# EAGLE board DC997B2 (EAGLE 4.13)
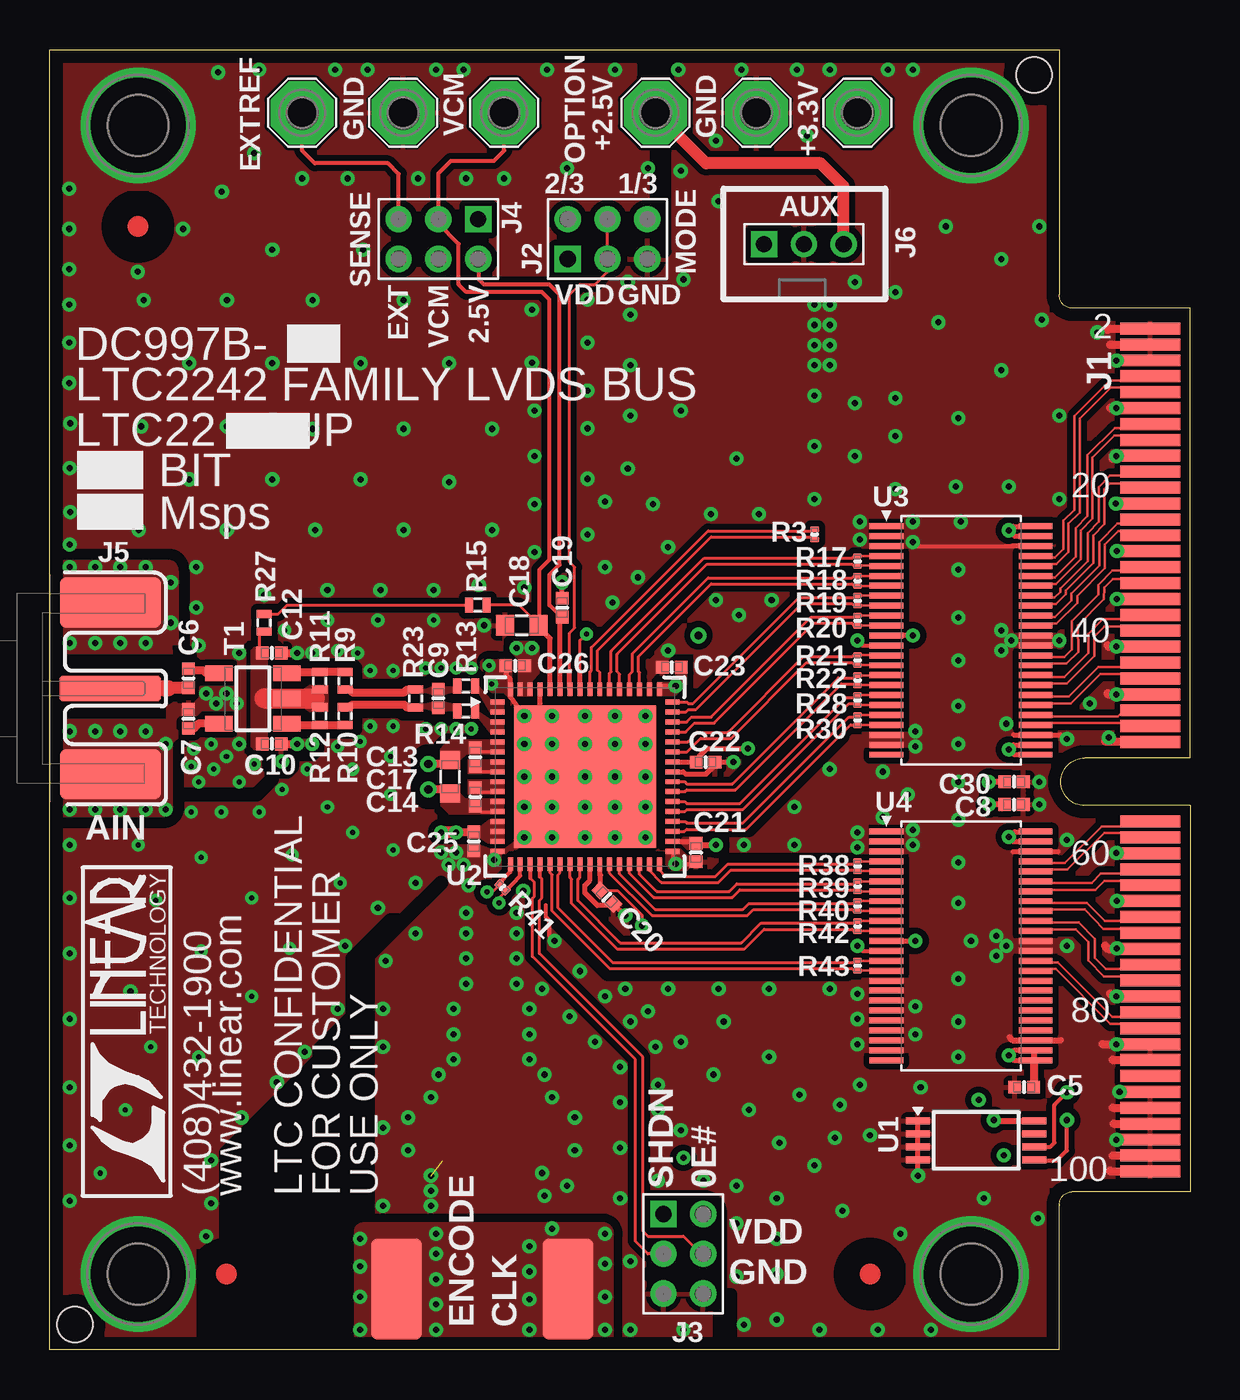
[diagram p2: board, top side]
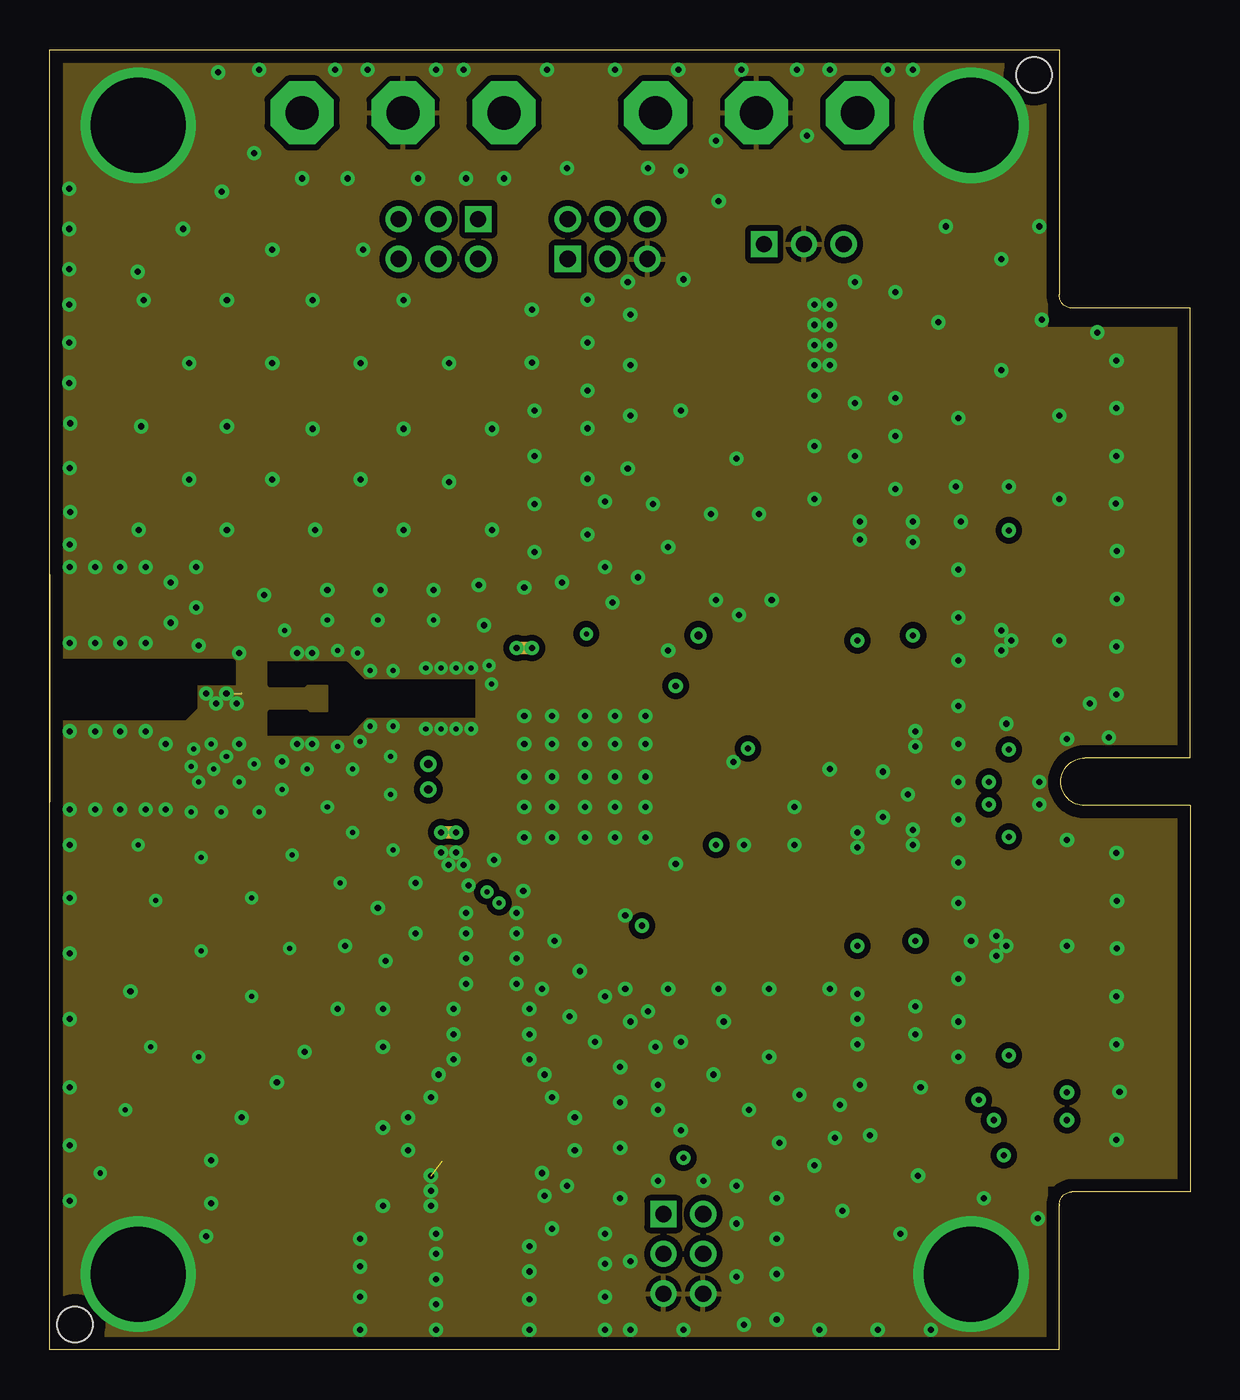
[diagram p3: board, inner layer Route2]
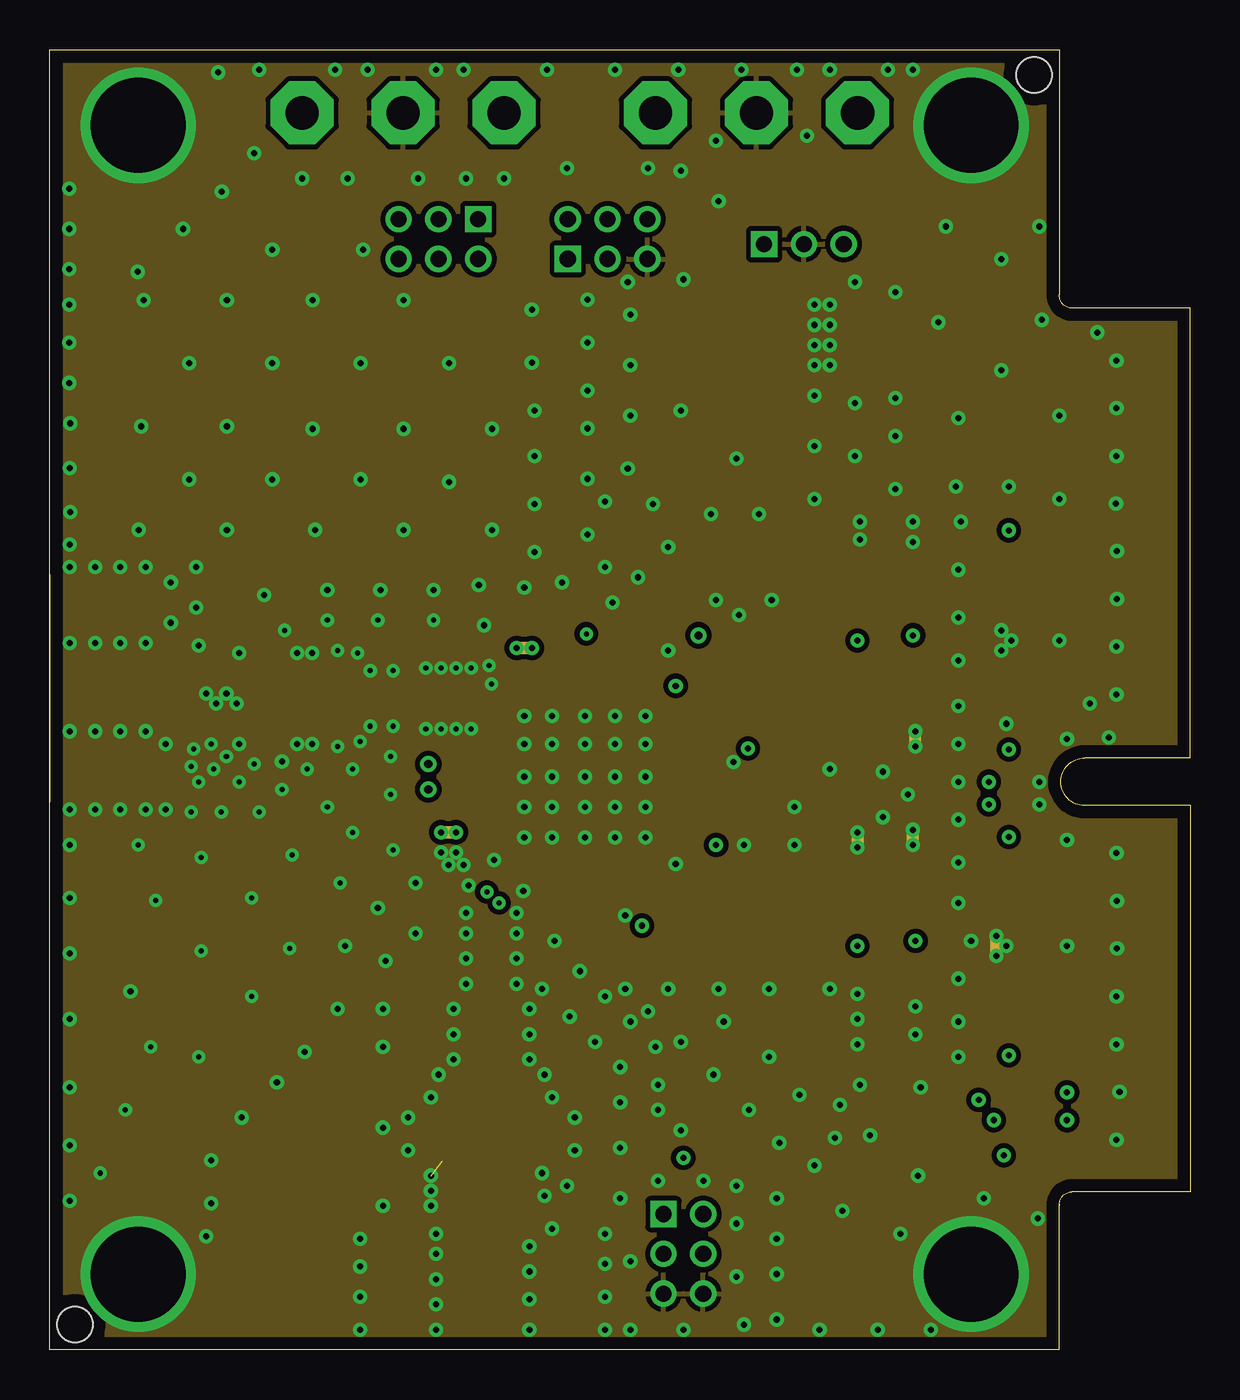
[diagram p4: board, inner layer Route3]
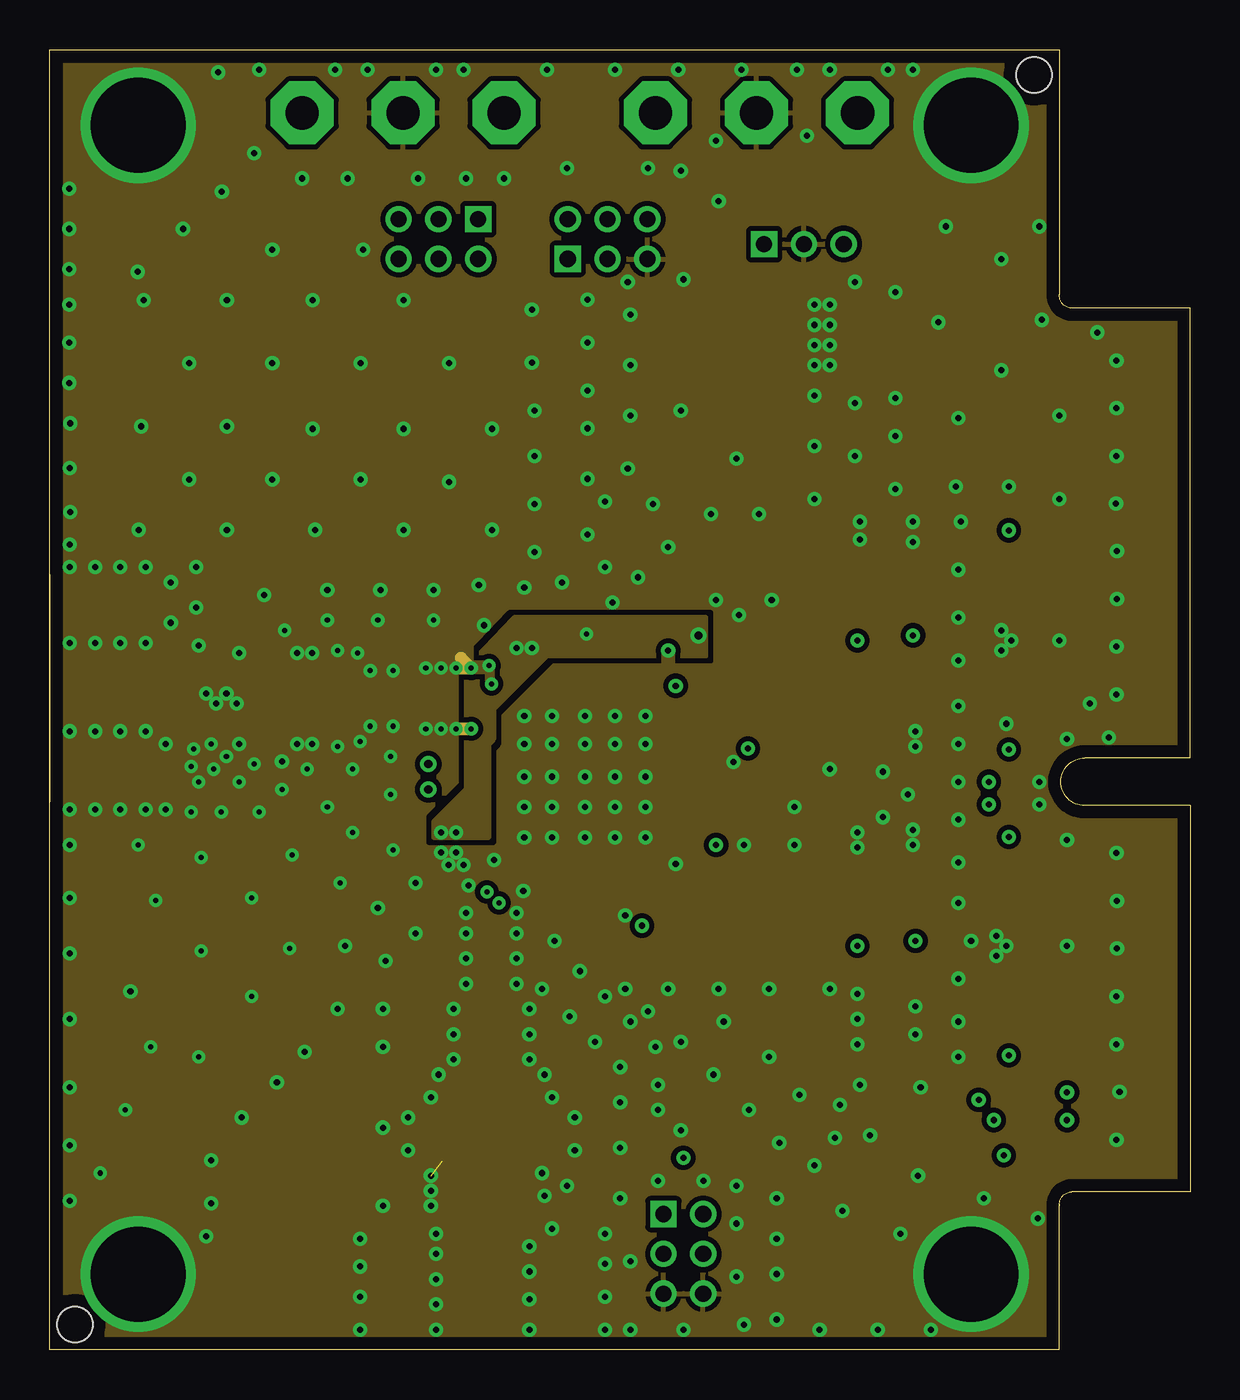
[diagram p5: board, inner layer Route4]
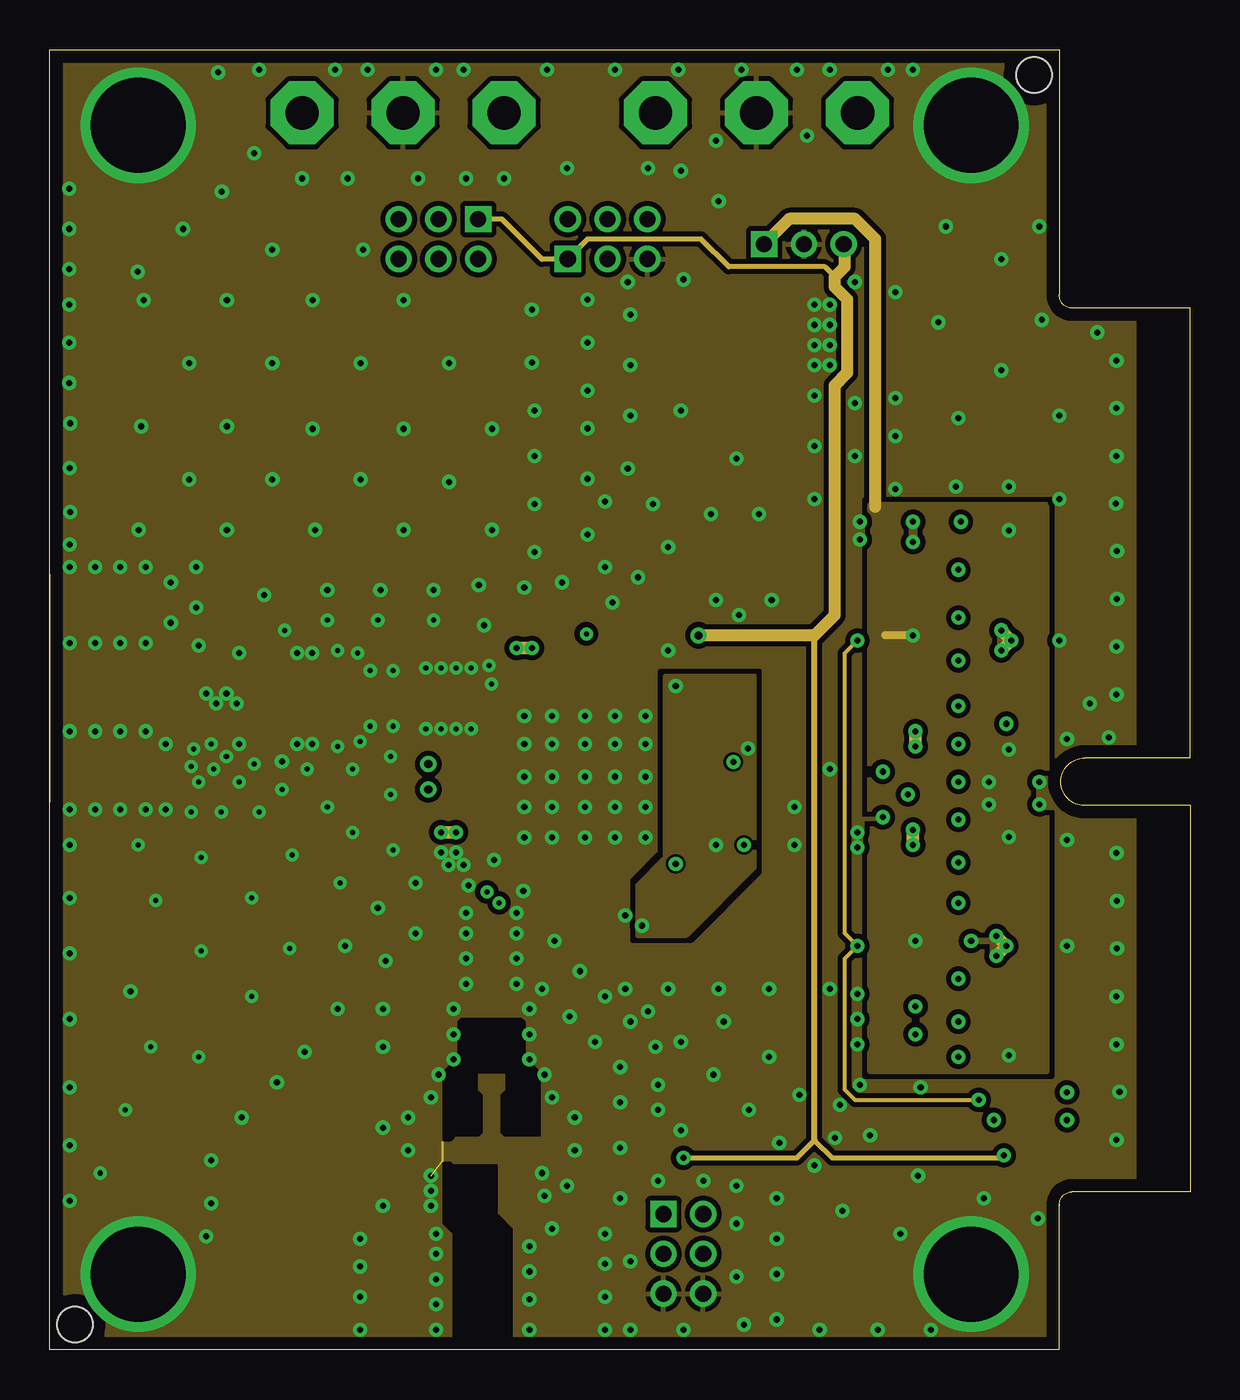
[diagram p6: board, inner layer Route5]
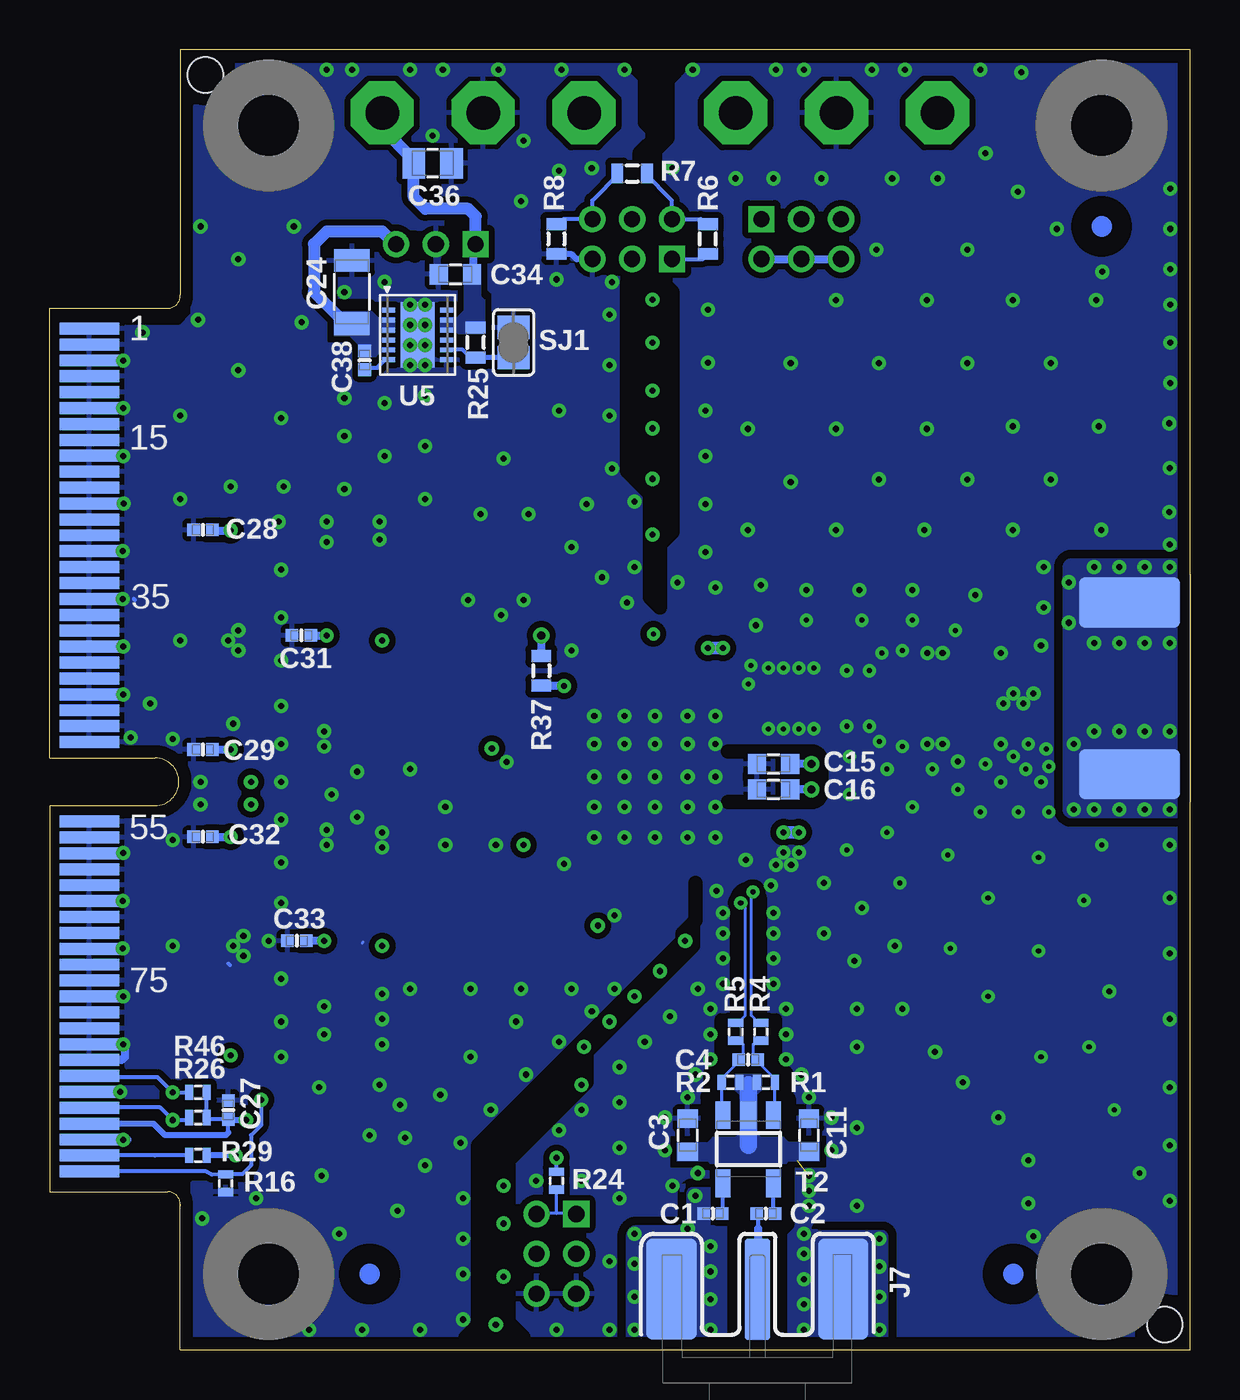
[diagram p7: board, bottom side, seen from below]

Size 57.37 x 65.41 mm. Coordinates in mm from the lower left corner, seen from the top.
Outline: 50.8,53.09 50.8,65.41 0,65.41 0,0 50.8,0 50.8,7.31
Copper layers (1+2*3+4*5+16): Top 0.035mm / dielectric 0.1524mm / Route2 0.035mm / dielectric 0.3556mm / Route3 0.035mm / dielectric 0.254mm / Route4 0.035mm / dielectric 0.3556mm / Route5 0.035mm / dielectric 0.1524mm / Bottom 0.035mm
Design rules "default": minimum track width 5mil, minimum drill 10mil, track to track 5mil, track to pad 5mil, pad to pad 5mil, via to via 5mil, smd to smd 5mil, copper to edge 25mil, drill to drill 15mil, minimum pad ring 10mil, minimum via ring 8mil, stop-mask expansion 3mil, vias tented up to drill 13mil, thermal gap 10mil
tRestrict: area 26.9,24.9 to 27.5,25.2; area 23.1,28.2 to 23.3,29.3; area 29.8,32.4 to 30.6,32.9; area 38.6,55 to 39.1,56.3; area 36.7,55 to 37.2,56.3; area 41.2,18.2 to 43,18.4; area 41.2,17.7 to 43,17.9; area 41.2,17.2 to 43,17.4; area 41.2,16.7 to 43,16.9; area 41.2,16.2 to 43,16.4; area 41.2,15.7 to 43,15.9; area 41.2,15.2 to 43,15.4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; 74 lines
bRestrict: area 20.8,14 to 23.6,16.6; area 25,0.6 to 36.4,21.5; area 25.4,37.3 to 28.3,64.8; area 43.2,53 to 43.3,54.1; area 41.3,52.3 to 42.7,52.6; 47 lines
vRestrict: area 6.7,31.5 to 25.5,37.8

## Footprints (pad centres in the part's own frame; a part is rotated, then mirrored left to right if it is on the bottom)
TOOLING_HOLE_0R067 = hole 1.778: 0,0
KEYSTONE_8831_GND = drill 4.775 pad 5.588 round: 1 0,0
C0402 = smd 0.635 x 0.635: 1 -0.472,0; 2 0.472,0
C0603 = smd 0.914 x 1.016: 1 -0.837,0; 2 0.837,0
C1206 = smd 1.143 x 1.778: 1 -1.591,0; 2 1.591,0
C0805 = smd 1.143 x 1.524: 1 -0.952,0; 2 0.952,0
MEC8-150-02-L-D-EDGE_CONN-NEW-ORIGIN = smd 3 x 0.6 bottom: 1 3.3,22.8; 3 3.3,22; 5 3.3,21.2; 7 3.3,20.4; 9 3.3,19.6; 11 3.3,18.8; 13 3.3,18; 15 3.3,17.2; 17 3.3,16.4; 19 3.3,15.6; 21 3.3,14.8; 23 3.3,14; 25 3.3,13.2; 27 3.3,12.4; 29 3.3,11.6; 31 3.3,10.8; 33 3.3,10; 35 3.3,9.2; 37 3.3,8.4; 39 3.3,7.6; 41 3.3,6.8; 43 3.3,6; 45 3.3,5.2; 47 3.3,4.4; 49 3.3,3.6; 51 3.3,2.8; 53 3.3,2; 55 3.3,-2; 57 3.3,-2.8; 59 3.3,-3.6; 61 3.3,-4.4; 63 3.3,-5.2; 65 3.3,-6; 67 3.3,-6.8; 69 3.3,-7.6; 71 3.3,-8.4; 73 3.3,-9.2; 75 3.3,-10; 77 3.3,-10.8; 79 3.3,-11.6; 81 3.3,-12.4; 83 3.3,-13.2; 85 3.3,-14; 87 3.3,-14.8; 89 3.3,-15.6; 91 3.3,-16.4; 93 3.3,-17.2; 95 3.3,-18; 97 3.3,-18.8; 99 3.3,-19.6 | smd 3 x 0.6: 2 3.3,22.8; 4 3.3,22; 6 3.3,21.2; 8 3.3,20.4; 10 3.3,19.6; 12 3.3,18.8; 14 3.3,18; 16 3.3,17.2; 18 3.3,16.4; 20 3.3,15.6; 22 3.3,14.8; 24 3.3,14; 26 3.3,13.2; 28 3.3,12.4; 30 3.3,11.6; 32 3.3,10.8; 34 3.3,10; 36 3.3,9.2; 38 3.3,8.4; 40 3.3,7.6; 42 3.3,6.8; 44 3.3,6; 46 3.3,5.2; 48 3.3,4.4; 50 3.3,3.6; 52 3.3,2.8; 54 3.3,2; 56 3.3,-2; 58 3.3,-2.8; 60 3.3,-3.6; 62 3.3,-4.4; 64 3.3,-5.2; 66 3.3,-6; 68 3.3,-6.8; 70 3.3,-7.6; 72 3.3,-8.4; 74 3.3,-9.2; 76 3.3,-10; 78 3.3,-10.8; 80 3.3,-11.6; 82 3.3,-12.4; 84 3.3,-13.2; 86 3.3,-14; 88 3.3,-14.8; 90 3.3,-15.6; 92 3.3,-16.4; 94 3.3,-17.2; 96 3.3,-18; 98 3.3,-18.8; 100 3.3,-19.6
HDR-3X2PS-2MM = drill 0.813 square: 1 -2,-1 | drill 0.813 round: 2 -2,1; 3 0,-1; 4 0,1; 5 2,-1; 6 2,1
SMA-FEMALE-EDGE-MNT = smd 5.08 x 1.27: 1 3.048,0 | smd 5.08 x 2.54: 2 3.048,4.318; 3 3.048,-4.318 | smd 5.08 x 2.54 bottom: 4 3.048,4.318; 5 3.048,-4.318
HDR-3X1PS-2MM = drill 0.813 square: 1 0,0 | drill 0.813 round: 2 2,0; 3 4,0
R0402 = smd 0.406 x 0.762: 1 -0.447,0; 2 0.447,0
R0201 = smd 0.279 x 0.432: 1 -0.254,0; 2 0.254,0
R0603 = smd 0.6 x 1: 1 -0.75,0; 2 0.75,0
SJ = smd 1.168 x 1.6: 1 -0.762,0; 2 0.762,0
MACOM_ETC1-XFMR = smd 0.762 x 1.397: 1 0,0; 2 1.27,0; 3 2.54,0; 4 2.54,-3.429; 5 0,-3.429
TURRET_MILLMAX_2308-2 = drill 1.676 pad 3.175 octagon: 1 0,0
TSSOP8 = smd 0.35 x 1.2: 1 -0.975,-2.925; 2 -0.325,-2.925; 3 0.325,-2.925; 4 0.975,-2.925; 5 0.975,2.925; 6 0.325,2.925; 7 -0.325,2.925; 8 -0.975,2.925
QFN_9X9 = smd 0.7 x 0.25: 1 -4.4,3.75; 2 -4.4,3.25; 3 -4.4,2.75; 4 -4.4,2.25; 5 -4.4,1.75; 6 -4.4,1.25; 7 -4.4,0.75; 8 -4.4,0.25; 9 -4.4,-0.25; 10 -4.4,-0.75; 11 -4.4,-1.25; 12 -4.4,-1.75; 13 -4.4,-2.25; 14 -4.4,-2.75; 15 -4.4,-3.25; 16 -4.4,-3.75; 33 4.4,-3.75; 34 4.4,-3.25; 35 4.4,-2.75; 36 4.4,-2.25; 37 4.4,-1.75; 38 4.4,-1.25; 39 4.4,-0.75; 40 4.4,-0.25; 41 4.4,0.25; 42 4.4,0.75; 43 4.4,1.25; 44 4.4,1.75; 45 4.4,2.25; 46 4.4,2.75; 47 4.4,3.25; 48 4.4,3.75 | smd 0.25 x 0.7: 17 -3.75,-4.4; 18 -3.25,-4.4; 19 -2.75,-4.4; 20 -2.25,-4.4; 21 -1.75,-4.4; 22 -1.25,-4.4; 23 -0.75,-4.4; 24 -0.25,-4.4; 25 0.25,-4.4; 26 0.75,-4.4; 27 1.25,-4.4; 28 1.75,-4.4; 29 2.25,-4.4; 30 2.75,-4.4; 31 3.25,-4.4; 32 3.75,-4.4; 49 3.75,4.4; 50 3.25,4.4; 51 2.75,4.4; 52 2.25,4.4; 53 1.75,4.4; 54 1.25,4.4; 55 0.75,4.4; 56 0.25,4.4; 57 -0.25,4.4; 58 -0.75,4.4; 59 -1.25,4.4; 60 -1.75,4.4; 61 -2.25,4.4; 62 -2.75,4.4; 63 -3.25,4.4; 64 -3.75,4.4 | smd 7.15 x 7.15: 65 0,0
TSSOP48 = smd 0.3 x 1.7: 1 -5.75,-3.75; 2 -5.25,-3.75; 3 -4.75,-3.75; 4 -4.25,-3.75; 5 -3.75,-3.75; 6 -3.25,-3.75; 7 -2.75,-3.75; 8 -2.25,-3.75; 9 -1.75,-3.75; 10 -1.25,-3.75; 11 -0.75,-3.75; 12 -0.25,-3.75; 13 0.25,-3.75; 14 0.75,-3.75; 15 1.25,-3.75; 16 1.75,-3.75; 17 2.25,-3.75; 18 2.75,-3.75; 19 3.25,-3.75; 20 3.75,-3.75; 21 4.25,-3.75; 22 4.75,-3.75; 23 5.25,-3.75; 24 5.75,-3.75; 25 5.75,3.75; 26 5.25,3.75; 27 4.75,3.75; 28 4.25,3.75; 29 3.75,3.75; 30 3.25,3.75; 31 2.75,3.75; 32 2.25,3.75; 33 1.75,3.75; 34 1.25,3.75; 35 0.75,3.75; 36 0.25,3.75; 37 -0.25,3.75; 38 -0.75,3.75; 39 -1.25,3.75; 40 -1.75,3.75; 41 -2.25,3.75; 42 -2.75,3.75; 43 -3.25,3.75; 44 -3.75,3.75; 45 -4.25,3.75; 46 -4.75,3.75; 47 -5.25,3.75; 48 -5.75,3.75
DE12 = smd 0.25 x 0.65: 1 -1.25,-1.45; 2 -0.75,-1.45; 3 -0.25,-1.45; 4 0.25,-1.45; 5 0.75,-1.45; 6 1.25,-1.45; 7 1.25,1.45; 8 0.75,1.45; 9 0.25,1.45; 10 -0.25,1.45; 11 -0.75,1.45; 12 -1.25,1.45 | smd 3.3 x 1.7: GP 0,0

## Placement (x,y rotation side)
-1  FIDUCIAL_0R040_O  [FIDUCIAL_0R040]  41.28,3.81 0 top
-2  FIDUCIAL_0R040_O  [FIDUCIAL_0R040]  8.89,3.81 0 top
-3  FIDUCIAL_0R040_O  [FIDUCIAL_0R040]  4.45,56.52 0 top
-8  TOOLING_HOLE_0R067  [TOOLING_HOLE_0R067]  49.53,64.14 0 top
-9  TOOLING_HOLE_0R067  [TOOLING_HOLE_0R067]  1.27,1.27 0 top
-10  STANDOFF_GND-KEYSTONE8831  [KEYSTONE_8831_GND]  4.45,61.6 90 top
-11  STANDOFF_GND-KEYSTONE8831  [KEYSTONE_8831_GND]  46.36,61.6 90 top
-12  STANDOFF_GND-KEYSTONE8831  [KEYSTONE_8831_GND]  46.36,3.81 90 top
-13  STANDOFF_GND-KEYSTONE8831  [KEYSTONE_8831_GND]  4.45,3.81 90 top
C1  0.1uF  [C0402]  24,6.86 0 bottom
C2  0.1uF  [C0402]  21.34,6.86 0 bottom
C3  0.1uF  [C0603]  25.27,10.79 90 bottom
C4  1.8pF  [C0402]  22.22,14.61 180 bottom
C5  0.1uF  [C0402]  49.02,13.21 180 top
C6  0.1uF  [C0402]  6.98,33.78 90 top
C7  0.1uF  [C0402]  6.98,31.75 90 top
C8  0.1uF  [C0402]  48.51,27.43 0 top
C9  1.8pF  [C0402]  19.56,32.77 270 top
C10  0.1uF  [C0402]  11.18,30.48 0 top
C11  0.1uF  [C0603]  19.18,10.79 90 bottom
C12  0.1uF  [C0402]  11.18,35.05 0 top
C13  0.1uF  [C0402]  21.41,29.82 90 top
C14  0.1uF  [C0402]  21.41,27.81 90 top
C15  1uF  [C0603]  20.95,29.46 180 bottom
C16  1uF  [C0603]  20.95,28.19 0 bottom
C17  2.2uF  [C0603]  20.14,28.83 270 top
C18  2.2uF  [C0603]  23.75,36.45 180 top
C19  0.1uF  [C0402]  25.78,37.34 90 top
C20  0.1uF  [C0402]  28.03,22.77 315 top
C21  0.1uF  [C0402]  32.51,25.02 270 top
C22  0.1uF  [C0402]  32.99,29.57 0 top
C23  0.1uF  [C0402]  31.3,34.34 180 top
C24  10uF  [C1206]  42.16,53.21 90 bottom
C25  0.1uF  [C0402]  21.34,25.58 90 top
C26  0.1uF  [C0402]  23.42,34.42 0 top
C27  0.1uF  [C0402]  48.39,12.06 90 bottom
C28  0.1uF  [C0402]  49.66,41.25 180 bottom
C29  0.1uF  [C0402]  49.66,30.2 180 bottom
C30  0.1uF  [C0402]  48.51,28.57 0 top
C31  0.1uF  [C0402]  44.7,35.94 180 bottom
C32  0.1uF  [C0402]  49.66,25.81 180 bottom
C33  0.1uF  [C0402]  44.93,20.57 180 bottom
C34  0.1uF  [C0603]  36.96,54.1 180 bottom
C36  4.7uF  [C0805]  38.1,59.69 0 bottom
C38  0.01uF  [C0402]  41.53,49.78 270 bottom
J1  MEC8-150-02-L-D-EDGE_CONNRE-DIM  [MEC8-150-02-L-D-EDGE_CONN-NEW-ORIGIN]  52.07,28.57 0 top
J2  2802S-06G2  [HDR-3X2PS-2MM]  28.07,55.88 0 top
J3  2802S-06G2  [HDR-3X2PS-2MM]  31.88,4.83 270 top
J4  2802S-06G2  [HDR-3X2PS-2MM]  19.56,55.88 180 top
J5  SMA  [SMA-FEMALE-EDGE-MNT]  0,33.27 0 top
J6  B03B-PASK  [HDR-3X1PS-2MM]  35.94,55.63 0 top
J7  SMA  [SMA-FEMALE-EDGE-MNT]  21.77,0 90 bottom
R1  49.9  [R0402]  21.34,13.46 180 bottom
R2  49.9  [R0402]  23.11,13.46 0 bottom
R3  100  [R0201]  38.48,41.02 270 top
R4  4.99  [R0402]  21.59,16 90 bottom
R5  4.99  [R0402]  22.86,16 90 bottom
R6  1000  [R0603]  24.26,55.88 90 bottom
R7  1000  [R0603]  28.07,59.18 0 bottom
R8  1000  [R0603]  31.88,55.88 270 bottom
R9  12.4  [R0402]  14.86,33.66 270 top
R10  12.4  [R0402]  14.86,31.88 90 top
R11  49.9  [R0402]  13.59,33.66 90 top
R12  49.9  [R0402]  13.59,31.88 270 top
R13  4.99  [R0402]  20.95,33.4 180 top
R14  4.99  [R0402]  20.95,32.13 180 top
R15  49.9  [R0402]  21.54,37.47 180 top
R16  100K  [R0402]  48.51,8.38 90 bottom
R17  100  [R0201]  40.64,39.67 270 top
R18  100  [R0201]  40.64,38.68 270 top
R19  100  [R0201]  40.64,37.69 270 top
R20  100  [R0201]  40.64,36.68 270 top
R21  100  [R0201]  40.64,34.7 270 top
R22  100  [R0201]  40.64,33.68 270 top
R23  100  [R0402]  18.41,32.77 90 top
R24  1000  [R0402]  31.88,8.51 90 bottom
R25  1000  [R0603]  35.94,50.67 90 bottom
R26  4990  [R0402]  49.91,11.68 0 bottom
R27  49.9  [R0402]  10.79,36.58 90 top
R28  100  [R0201]  40.64,32.69 270 top
R29  4990  [R0402]  49.91,9.78 0 bottom
R30  100  [R0201]  40.64,31.67 270 top
R37  BLM18BB470SN1D  [R0603]  32.64,34.16 270 bottom
R38  100  [R0201]  40.64,24.33 270 top
R39  100  [R0201]  40.64,23.32 270 top
R40  100  [R0201]  40.64,22.33 270 top
R41  100  [R0201]  22.78,23.27 135 top
R42  100  [R0201]  40.64,21.31 270 top
R43  100  [R0201]  40.64,19.33 270 top
R46  4990  [R0402]  49.91,12.95 180 bottom
SJ1  [SJ]  34.04,50.67 270 bottom
T1  MABA-007159-000000  [MACOM_ETC1-XFMR]  11.94,34.04 270 top
T2  MABA-007159-000000  [MACOM_ETC1-XFMR]  23.5,11.81 0 bottom
TP1  TURRET0.063  [TURRET_MILLMAX_2308-2]  12.7,62.23 0 top
TP2  TURRET0.063  [TURRET_MILLMAX_2308-2]  17.78,62.23 0 top
TP3  TURRET0.063  [TURRET_MILLMAX_2308-2]  30.48,62.23 0 top
TP4  TURRET0.063  [TURRET_MILLMAX_2308-2]  35.56,62.23 0 top
TP5  TURRET0.063  [TURRET_MILLMAX_2308-2]  40.64,62.23 0 top
TP6  TURRET0.063  [TURRET_MILLMAX_2308-2]  22.86,62.23 90 top
U1  24LC02ST  [TSSOP8]  46.61,10.54 270 top
U2  LTC2242CUP-12  [QFN_9X9]  26.92,28.83 0 top
U3  FIN1108  [TSSOP48]  45.85,35.69 270 top
U4  FIN1108  [TSSOP48]  45.85,20.32 270 top
U5  LT1763CDE  [DE12]  38.86,51.05 270 bottom
U$3  [LT-LOGO]  6.1,7.75 90 top
U$4  [ARTWORK_TITLEBLOCK]  not placed on the board
U$5  [LETTER_L]  not placed on the board
U$6  [ANSI-DOC-FIELD]  not placed on the board
U$8  [REVISION-HISTORY]  not placed on the board
U$9  [FAB-NOTES-AU-THERMAL]  not placed on the board
U$15  [STACKUP-6LAYER]  not placed on the board

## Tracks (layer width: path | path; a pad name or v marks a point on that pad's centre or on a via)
+2.5V  (via drill 0.25, 0.3, 0.41)
  Top 0.152: 26.67,34.16 26.67,34.54 26.67,34.67 26.67,35.69 v27,36.02
  Top 0.254: U2.57 26.67,34.16 | C25.2 21.32,26.04
  Top 0.406: 21.32,26.04 v20.45,26.04
  Top 0.61: v20.45,26.04 v19.68,26.04 | TP3.1 33.02,59.69 38.79,59.69 39.93,58.55 39.93,55.63 J6.3
  Route2 0.635: v23.5,35.31 v24.26,35.31 | v19.68,26.04 v20.45,26.04
  Route3 0.635: v19.68,26.04 v20.45,26.04 | v23.5,35.31 v24.26,35.31
  Route5 0.254: v48.01,9.78 47.88,9.65 39.37,9.65 38.48,10.54 37.59,9.65 v31.88,9.65 | 39.5,53.98 38.99,54.48 34.16,54.48 32.77,55.88 27.05,55.88 26.07,54.9 J2.1 26.05,54.86 24.77,54.86 22.75,56.88 J4.1
  Route5 0.305: 38.48,10.54 38.48,35.94
  Route5 0.61: v32.64,35.94 38.48,35.94 39.5,36.96 39.5,48.51 40.13,49.15 40.13,52.83 39.5,53.47 39.5,53.98 40.01,54.48 40.01,55.5 39.88,55.63 J6.3
  Route5 0.635: v23.5,35.31 v24.26,35.31 | v20.45,26.04 v19.68,26.04
  Bottom 0.203: R6.1 24.26,55.12 24.5,54.88 J2.1 | R24.2 31.87,9.39 v31.88,9.65
  Bottom 0.305: v48.01,9.78 R29.2
  Bottom 0.406: v32.64,35.94 R37.1
  Bottom 0.61: J6.3 40.01,55.63 40.64,56.26 43.43,56.26 44.07,55.63 44.07,53.21 42.48,51.62 C24.1
  Bottom 0.635: v19.68,26.04 v20.45,26.04 | v23.5,35.31 v24.26,35.31
  pour Top (no thermals): 21.06,26.34 21.67,26.34 22.12,26.67 22.86,26.67 22.86,25.48 22.05,25.48 21.64,25.76 21.06,25.76
  pour Top (rank 2, no thermals): 24.28,32.89 24.28,33.68 24.64,34.04 24.64,35.38 24.38,35.64 23.37,35.64 23.16,35.43 23.16,35.15 23.6,34.72 23.6,34.09 23.57,34.06 23.57,32.89
  pour Bottom (no thermals): 40.03,51.89 40.84,51.89 41.15,52.2 43.05,52.2 43.05,51.05 42.29,51.05 41.91,50.67 41.78,50.55 41.78,50.04 41.78,49.99 40.97,49.99 40.74,50.22 40.03,50.22 40.03,50.39 40.69,50.39 40.82,50.52 40.82,51.13 40.74,51.21 40.03,51.21 40.03,51.84 40.06,51.87
  pour Route4 (isolate 0.254): 33.02,36.83 23.37,36.83 20.95,34.29 20.95,28.19 19.3,26.54 19.3,25.78 22.1,25.78 22.1,30.48 22.35,30.73 22.35,32.26 25.02,34.93 33.02,34.93
+3.3V  (via drill 0.3)
  Top 0.254: U3.26 48.5,30.44 v48.26,30.2 48.54,29.95 U3.25 | U4.47 48.47,25.57 v48.26,25.81 48.54,26.06 U4.48 | U3.47 48.55,40.94 v48.26,41.22 48.46,41.43 49.61,41.43 U3.48 | U4.25 48.5,14.57 v48.26,14.81 48.51,15.06 49.53,15.06 U4.26 | U4.26 | U4.26 | U4.12 43.3,20.57 v43.56,20.57 | U3.12 43.3,35.94 v43.43,35.94
  Top 0.305: U4.26 49.61,15.07 49.53,15.06 49.53,14.35 | 48.13,28.57 C30.1 v47.24,28.57 | 48.13,27.43 C8.1 v47.24,27.43
  Top 0.406: C5.1 49.53,13.33 49.53,14.35
  Route5 0.406: v43.43,35.94 42.04,35.94
  Route5 0.61: J6.1 37.21,56.9 40.51,56.9 41.53,55.88 41.53,42.42
  Bottom 0.406: C28.1 49.16,41.22 v48.26,41.22 | C29.1 v48.26,30.2 | C32.1 v48.26,25.81 | C31.1 v43.43,35.94 | v43.56,20.57 C33.1 | C34.1 36.07,54.1 36.07,55.5 J6.1
  Bottom 0.61: TP5.1 40.64,61.47 39.05,59.88 C36.1 39.05,57.98 38.48,57.4 36.32,57.4 35.94,57.02 35.94,55.75 35.81,55.63 J6.1
  pour Bottom (no thermals): 37.69,51.23 36.91,51.23 36.83,51.16 35.48,51.16 35.48,52.78 35.69,52.98 35.69,54.56 36.5,54.56 36.5,52.27 36.88,51.89 37.69,51.89 37.69,51.26 37.67,51.23
  pour Route5 (isolate 0.254): 48.9,13.97 41.28,13.97 41.28,42.55 50.17,42.55 50.17,13.97
AIN+
  pour Top (no thermals): 21.56,33.76 21.23,33.76 21.23,33.05 21.56,33.05 22.2,31.98 22.86,31.98 22.86,32.69 22.2,32.69 21.56,33.4
AIN-
  pour Top (no thermals): 22.86,31.67 22.2,31.67 21.59,32.08 21.59,32.49 21.23,32.49 21.23,31.78 21.56,31.78 22.2,30.99 22.83,30.99 22.86,31.01
EXT_REF
  Top 0.203: J4.5 17.56,59.15 17.02,59.69 13.33,59.69 12.7,60.33 TP1.1
GND  (via drill 0.25, 0.25 pad 0.25, 0.3)  (1 unrouted)
  Top 0.203: U2.25 | U2.65 27.18,28.57 | U2.41 | 27.56,29.08 27.3,28.83 U2.65 | C21.2 32.38,24.43 v31.5,24.43 31.37,24.51 31.37,25.03 U2.33 | U2.65 30.17,28.83 | U2.65 24.67,31.08 | U3.46 43.64,40.44 v43.43,40.64 | J1.35 53.68,37.78 53.67,37.77 | J1.35 55.37,37.72 | J1.35 55.31,37.72 53.72,37.72 | 24.97,22.38 24.97,21.77 25.15,21.59 25.15,20.83 v25.4,20.57
  Top 0.254: 24.67,31.08 U2.61 | v23.88,31.88 23.17,32.83 U2.64 23.17,33.72 22.99,33.91 22.99,34.42 C26.1 | v29.97,25.78 30.35,25.4 | 42.09,15.57 42.06,15.57 | 42.04,16.56 42.06,16.56 | 42.09,17.07 42.11,17.07 | 42.11,17.58 42.06,17.58 | 48.46,25.07 49.63,25.07 | 49.63,25.07 50.72,25.07 | 49.63,25.07 49.63,25.04 U4.46 | 48.49,30.94 49.58,30.94 | 49.58,30.94 50.83,30.94 | 49.58,30.94 49.58,30.96 49.6,30.96 U3.27 | U3.46 | U3.46 48.44,40.44 | 53.67,37.77 53.72,37.72 53.78,37.78 J1.35 | 33.63,29.57 v34.39,29.57 34.42,29.59 | U2.41 31.88,29.08 32,28.96 33.02,28.96 33.63,29.57 | 33.63,29.57 33.53,29.59 | 33.63,29.57 C22.2 | C20.2 v28.96,21.84 | U2.25 27.17,23.62 26.92,23.37 26.92,22.99 27.56,22.35 28.19,22.35 28.32,22.48 C20.2 | C20.2 | C19.2 v25.78,38.61 | v43.69,8.76 43.69,9.53 43.68,9.53 U1.4 U1.3 | U1.3 43.68,10.28 43.69,10.29 | U1.3 U1.2 | U1.2 43.68,10.92 43.69,10.92 | 43.68,11.55 U1.1 | U1.2 43.68,11.55 | 43.68,11.55 43.69,11.56
  Top 0.305: 42.16,18.57 42.09,18.57 | C5.2 48.66,13.24 48.72,13.31 | U4.27 48.44,15.57 48.29,15.72 | 49.58,15.57 50.88,15.57
  Top 0.406: 53.75,12.95 55.35,12.95 J1.89 53.74,12.97 | J1.59 55.33,24.99 v53.67,24.99 | J1.65 55.34,22.61 53.85,22.58 53.65,22.58 | 53.75,20.19 55.35,20.19 J1.71 53.23,20.18 53.09,20.32 | 53.75,17.78 J1.77 53.47,17.77 53.34,17.91 | 55.25,30.48 55.28,30.48 J1.53 55.34,30.61 53.09,30.61 | J1.11 53.34,47.38 v53.67,47.37 | J1.5 53.46,49.78 v53.67,49.76 | J1.1 53.28,51.38 53.21,51.31 | J1.17 53.48,44.98 53.47,44.83 | J1.23 53.62,42.58 v53.65,42.57 | 53.59,35.38 53.27,35.38 53.21,35.43 | 53.59,35.38 J1.41 v53.66,35.38 53.59,35.31 53.59,35.38 | J1.47 53.26,32.98 53.21,33.02 | J1.29 53.64,40.18 v53.7,40.18 | J1.4 53.37,50.58 53.34,50.55 | 53.74,12.97 53.75,12.98 v53.82,12.98 | 53.74,12.97 53.72,12.95 | J1.85 53.5,14.57 53.47,14.61 | 53.72,15.37 53.7,15.37 53.76,15.38 J1.83 53.73,15.38 53.72,15.37 | 52.96,15.37 53.72,15.37 | J1.92 53.48,12.17 53.47,12.19 | J1.94 53.52,11.38 53.54,11.38 | J1.98 53.47,9.78 | J1.100 53.38,8.97 53.34,9.02 | C12.2 v12.45,35.05 | C10.2 v12.45,30.48 | v53.67,10.57 J1.95 53.76,10.57 53.72,10.54 53.7,10.57 v53.67,10.57
  Route2 0.102: v8.89,33.02 9.65,33.02
  Route3 0.61: v47.62,19.81 v47.62,20.83 | v40.64,26.04 v40.64,25.27 | v43.56,30.35 v43.56,31.11 | v43.43,25.4 v43.43,26.16
  Route4 0.635: v20.45,34.29 v21.21,34.29 20.7,34.8 | v21.21,31.24 v20.45,31.24
  Route5 0.127: 19.76,9.5 19.76,10.44
  Route5 0.635: v47.88,36.2 v48.39,35.69 v47.88,35.18 | v47.62,20.83 v48.13,20.32 v47.62,19.81 | v43.56,30.35 v43.56,31.11 | v43.43,25.4 v43.43,26.16
  Bottom 0.127: 41.6,20.51 41.66,20.45
  Bottom 0.203: 48.32,19.36 48.39,19.43 | 53.09,37.72 53.14,37.78 | J1.35 53.78,37.78 53.72,37.72
  Bottom 0.305: 31.88,55.12 31.11,55.12 30.86,54.86 30.35,54.86 | 30.35,54.86 30.1,54.86 | J2.5 29.99,54.88 29.97,54.86 30.35,54.86
  Bottom 0.406: v53.83,12.97 J1.89 53.87,12.97 53.85,12.95 v53.82,12.98 | J1.95 53.45,10.57 v53.67,10.57 | J1.85 53.75,14.57 53.59,14.73 53.59,15.24 53.72,15.37 | v53.67,15.37 53.72,15.37 | J1.83 53.73,15.38 53.72,15.37 | 53.72,15.37 53.59,15.37
  other vias: 29.97,31.88 26.92,31.88 25.27,31.88 28.45,31.88 23.88,27.3 29.97,27.3 26.92,27.3 25.27,27.3 28.45,27.3 43.43,41.66 23.88,30.48 29.97,30.48 26.92,30.48 25.27,30.48 28.45,30.48 23.88,28.83 29.97,28.83 25.27,28.83 28.45,28.83 23.88,25.78 26.92,25.78 25.27,25.78 28.45,25.78 38.74,1.02 41.66,1.02 44.32,1.02 46.99,7.62 42.8,5.84 1.04,46.61 0.99,48.64 1.02,44.35 1.04,42.14 0.99,58.42 22.22,33.5 1.02,7.49 1.02,10.29 1.02,22.73 1.02,13.21 1.02,16.64 10.29,60.2 10.54,64.39 18.54,58.93 14.99,58.93 12.7,58.93 14.35,64.39 16,64.39 19.43,64.39 20.83,64.39 25.02,64.39 28.45,64.39 31.62,64.39 34.8,64.39 37.59,64.39 39.24,64.39 42.16,64.39 43.43,64.39 30.1,59.44 26.04,59.44 20.95,58.93 22.86,58.93 52.71,51.18 1.02,19.94 1.02,25.4 4.06,18.03 53.67,17.78 53.7,20.19 53.7,22.58 53.67,32.97 53.67,44.96 53.29,30.81 49.78,27.43 49.78,28.57 53.7,37.77 48.13,31.5 40.64,15.37 40.64,16.64 40.64,17.91 43.56,17.27 51.18,20.32 45.72,18.67 40.77,41.66 51.18,30.73 52.32,32.51 50.8,42.8 51.18,25.65 49.71,6.6 50.8,35.69 45.85,41.66 45.72,39.24 45.72,36.83 45.72,34.67 45.72,32.38 45.72,30.48 45.72,28.57 45.72,26.67 45.72,24.51 45.72,16.51 45.72,22.48 46.36,20.57 45.72,14.73 26.92,28.83 19.68,31.24 18.92,31.24 31.11,35.18 19.68,25.02 20.45,25.02 20.07,24.38 21.84,36.45 20.83,24.38 7.87,33.02 8.38,32.51 13.21,35.05 13.21,30.48 40.77,40.77 43.56,15.88 9.53,35.05 9.53,30.48 9.4,32.51 18.92,34.29 19.68,34.29 22.1,34.42 19.18,12.7 25.27,12.7 1.02,39.37 2.29,39.37 3.56,39.37 4.83,39.37 1.02,35.56 2.29,35.56 3.56,35.56 4.83,35.56 1.02,27.18 2.29,27.18 3.56,27.18 4.83,27.18 4.83,31.11 3.56,31.11 2.29,31.11 1.02,31.11 5.84,30.48 6.1,38.61 6.1,36.58 5.84,27.18 15.62,1.02 15.62,2.67 15.62,4.19 15.62,5.59 19.43,5.84 27.94,1.02 27.94,2.67 27.94,4.32 27.94,5.84 25.27,6.1 24.13,1.02 24.13,2.54 24.13,3.94 24.13,5.21 19.43,1.02 19.43,2.29 19.43,3.56 19.43,4.83 20.32,17.14 24.13,17.14 24.13,15.88 20.32,15.88 20.32,14.61 24.13,14.61 20.95,18.41 23.5,18.41 20.95,19.68 23.5,19.68 20.95,20.95 23.5,20.95 23.5,21.97 20.95,21.97 22.35,24.64 21.08,23.37 19.56,13.84 24.89,13.84 18.03,11.68 26.42,11.68 26.42,10.03 18.03,10.03 19.18,8.76 24.77,8.89 19.18,7.24 19.18,8 24.89,7.75 26.04,8.26 28.7,14.22 27.43,15.49 26.16,16.76 24.77,18.16 28.7,12.45 28.7,10.16 28.7,7.62 29.21,1.02 31.88,1.02 29.21,4.45 30.61,12.06 30.61,8.51 32.89,8.51 31.75,11.05 36.58,1.52 36.7,10.41 36.58,7.62 36.58,5.59 36.58,3.81 35.18,12.06 33.4,13.84 31.75,15.49 30.1,17.02 28.96,18.16 26.67,19.05 27.94,17.78 29.21,16.51 30.48,15.24 30.61,13.33 34.93,1.27 34.54,3.68 34.54,6.35 34.54,8.26 31.11,18.16 33.66,18.16 36.2,18.16 39.24,18.16 34.93,25.4 37.47,25.4 37.47,27.3 39.24,29.21 41.91,29.08 41.91,26.8 43.18,27.94 36.32,37.72 33.53,37.72 34.67,36.96 40.51,47.62 40.51,44.96 42.55,43.31 45.59,43.43 48.26,43.43 42.55,47.88 42.55,45.97 38.48,42.8 38.48,45.47 38.48,48.01 33.27,42.04 35.69,42.04 31.11,40.39 28.32,37.59 29.59,38.86 27.94,39.37 27.94,42.67 29.08,44.32 29.21,46.99 29.21,49.53 29.21,52.07 27.05,41.02 27.05,43.82 27.05,46.36 27.05,48.26 27.05,50.67 27.05,52.83 29.08,53.72 24.26,52.32 24.26,49.66 24.38,47.24 24.38,44.96 24.38,42.55 24.38,40.13 23.88,38.35 21.59,38.48 19.3,38.23 16.64,38.23 13.97,38.23 10.79,37.97 7.49,35.43 7.37,37.34 7.37,39.37 1.02,40.51 0.99,56.39 0.99,54.36 0.99,52.58 0.99,50.67 4.42,54.23 6.71,56.39 8.48,64.26 22.25,41.25 17.81,41.25 13.36,41.25 8.92,41.25 4.47,41.25 7.01,43.79 11.2,43.79 15.65,43.79 20.09,43.66 22.25,46.33 17.81,46.33 13.23,46.33 8.92,46.46 4.6,46.46 7.01,49.63 11.2,49.63 15.65,49.63 20.09,49.63 13.23,52.81 8.92,52.81 4.72,52.81 11.2,55.35 8.66,58.27 17.81,52.81 15.77,55.35 30.35,42.55 34.54,44.83 31.75,47.24 31.88,53.85 47.88,49.28 50.8,46.99 45.72,46.86 44.7,51.69 47.88,54.86 49.91,51.82 49.78,56.52 31.75,59.31 33.66,57.79 33.53,60.83 38.1,61.09 33.91,16.51 36.2,14.73 37.72,12.83 38.48,9.27 39.88,6.98 18.41,23.5 18.41,20.95 16.51,22.22 16.89,19.56 14.86,20.32 14.48,17.14 16.76,17.14 16.76,15.24 12.83,14.99 11.43,13.46 9.65,11.68 8.13,9.53 7.87,5.71 8.13,7.37 16.76,7.24 16.76,11.18 11.68,29.59 16.13,31.37 16.13,34.16 17.27,34.16 17.27,31.37 14.48,30.35 14.48,35.18 15.49,35.05 15.62,30.61 12.95,29.21 11.68,28.19 7.24,30.23 9.53,28.57 8.26,29.21 8.89,29.84 10.29,29.46 8.13,30.48 7.49,28.57 7.11,29.34 7.11,27.05 8.64,27.05 10.54,27.05 17.14,29.84 17.14,27.94 17.27,25.15 15.24,26.04 15.24,29.21 13.97,27.3 14.61,23.5 12.19,24.89 4.45,25.4 7.62,24.77 10.16,22.73 5.33,22.61 12.06,20.19 7.62,20.07 10.16,17.78 5.08,15.24 3.81,12.06 7.49,14.73 2.54,8.89 38.48,52.58 39.24,52.58 39.24,51.56 38.48,51.56 38.48,49.53 39.24,49.53 39.24,50.55 38.48,50.55 42.55,53.21 40.51,53.72 39.75,12.32 39.5,10.67 41.28,10.79 40.77,13.33 43.82,13.21 11.81,36.2 13.97,36.7 16.51,36.7 19.3,36.7 23.83,23.09 45.09,56.52
  pour Route2 (isolate 0.305): 0.64,64.77 50.17,64.77 50.17,51.44 57.15,51.44 57.15,8.26 50.17,8.26 50.17,0.64 0.64,0.64 0.51,31.62 6.86,31.62 7.49,32.26 7.49,33.4 9.4,33.4 9.4,30.86 15.11,30.86 16,31.75 21.46,31.75 21.46,33.78 15.88,33.78 14.99,34.67 9.4,34.67 9.27,34.8 0.64,34.8
  pour Bottom (isolate 0.305, rank 2): 50.17,64.77 50.17,52.07 50.8,51.44 56.64,51.44 56.64,30.1 52.07,30.1 arc180 51.94,27.05 56.64,27.05 56.64,12.45 46.99,12.45 46.99,8.38 50.17,8.38 50.17,0.64 0.64,0.64 0.64,64.77
  pour Top (no thermals): 40.89,18.67 43.31,18.67 43.31,14.99 40.89,14.99
  pour Top (no thermals): 40.89,26.67 40.89,24.99 43.31,24.99 43.31,26.67
  pour Top (no thermals): 48.44,20.65 50.77,20.65 50.77,19.99 48.41,19.99 48.41,20.65
  pour Top (no thermals): 40.92,31.04 43.28,31.04 43.28,30.35 40.92,30.35
  pour Top (no thermals): 50.75,35.36 50.88,35.38 51.05,35.56 51.05,35.81 50.75,36.02 48.44,36.02 48.44,35.36
  pour Top (no thermals): 40.89,42.16 40.89,40.36 43.31,40.36 43.31,42.16
  pour Top (no thermals): 23.47,25.63 22.89,25.2 22.17,25.2 21.62,25.4 19.3,25.4 19.3,24.51 19.81,24 21.72,24 21.84,24.13 22.61,24.13 22.73,24.26 22.73,24.89 22.81,24.97 22.96,24.97 23.16,25.17 23.5,25.17 23.55,25.22 23.8,25.43
  pour Top (no thermals): 43.18,64.64 49.91,64.64 49.91,58.42 43.18,58.42
  pour Top (no thermals): 43.18,7.37 43.18,0.64 50.17,0.64 50.17,7.37
  pour Bottom (no thermals): 10.67,0.64 0.64,0.64 0.64,6.98 10.67,6.98
  pour Bottom (no thermals): 0.64,64.77 9.53,64.77 9.53,54.74 0.64,54.74
  pour Bottom (no thermals): 43.18,64.77 50.17,64.77 50.17,57.79 43.18,57.79
  pour Bottom (no thermals): 50.17,7.62 42.04,7.62 39.5,5.08 39.5,0.64 50.17,0.64
  pour Route2 (no thermals): 0.64,64.77 7.62,64.77 7.62,58.04 0.64,58.04
  pour Route2 (no thermals): 7.62,0.64 7.62,6.98 0.64,6.98 0.64,0.64
  pour Route2 (no thermals): 50.17,0.64 50.17,6.98 43.18,6.98 43.18,0.64
  pour Route2 (no thermals): 50.17,64.77 50.17,58.42 43.18,58.42 43.18,64.77
  pour Bottom (no thermals): 0.64,26.8 0.64,39.88 6.35,39.88 6.35,26.8
  pour Bottom (no thermals): 14.73,0.66 10.03,0.66 10.03,2.67 14.73,2.67
  pour Top (no thermals): 9.78,35.18 9.53,35.18 9.53,33.4 9.4,33.27 7.62,33.27 7.62,32.77 7.24,32.38 6.1,32.38 5.46,31.75 0.64,31.75 0.64,26.92 5.59,26.92 5.59,31.11 6.48,32 7.37,32 7.62,32.26 9.4,32.26 9.53,32.13 9.53,30.35 9.78,30.35
  pour Top (no thermals): 32.82,24.84 32.08,24.84 31.75,25.17 31.72,25.2 30.99,25.2 30.99,24.43 31.32,24.1 32.05,24.1 32.21,24.26 32.82,24.26
  pour Top (no thermals): 30.28,32.89 30.28,33.76 30.56,34.04 31.11,34.04 31.11,34.7 31.34,34.93 31.34,35.28 31.17,35.46 30.94,35.46 30.07,34.59 30.07,32.89
  pour Top (no thermals): 23.27,32.84 23.27,34.72 21.77,34.72 21.64,34.59 21.64,34.26 22.05,33.86 22.05,33.25 22.22,33.07 22.83,33.07 23.06,32.84
  pour Bottom (no thermals): 24.26,0.76 28.45,0.76 28.45,6.35 25.53,6.35 25.53,8.26 24.26,8.26 24.26,0.89 24.38,0.76
  pour Bottom (no thermals): 15.62,0.64 19.3,0.64 19.3,5.97 15.11,5.97 15.11,0.64 15.75,0.64
  pour Route3 (isolate 0.254): 0.64,64.77 50.17,64.77 50.17,52.71 arc90 50.8,52.07 57.15,52.07 57.15,8.26 51.18,8.26 arc90 50.42,7.49 50.42,0.64 0.64,0.64
  pour Route4 (isolate 0.254, rank 2): 0.64,64.77 50.17,64.77 50.17,52.71 50.8,52.07 57.15,52.07 57.15,8.26 50.8,8.26 50.17,7.62 50.17,0.64 0.64,0.64
  pour Top (isolate 0.305, rank 5): 0.64,64.77 50.17,64.77 50.17,52.07 57.15,52.07 57.15,8.26 50.17,8.26 50.17,0.64 0.64,0.64
  pour Top (no thermals): 0.64,39.88 6.48,39.88 6.48,35.56 0.64,35.56
  pour Top (no thermals): 0.64,31.11 6.35,31.11 6.35,26.54 0.64,26.54
  pour Top (no thermals): 15.24,0.76 15.24,6.48 28.45,6.48 28.45,0.76
  pour Route2: 9.4,34.8 9.4,30.73 10.92,30.73 10.92,32.13 11.05,32.26 12.95,32.26 13.08,32.13 13.97,32.13 13.97,33.4 12.95,33.4 12.83,33.27 11.05,33.27 10.92,33.4 10.92,34.8
  pour Route5 (isolate 0.254, rank 2): 50.17,64.77 0.64,64.77 0.64,0.76 0.51,0.64 20.19,0.64 20.19,5.84 19.68,6.35 19.68,13.97 20.45,14.73 20.45,16.51 20.7,16.76 23.75,16.76 24,16.51 24,14.73 24.77,13.97 24.77,10.67 22.86,10.67 22.61,10.92 22.61,12.83 22.86,13.08 22.86,13.84 21.59,13.84 21.59,13.08 21.84,12.83 21.84,10.92 21.59,10.67 20.45,10.67 20.19,10.41 19.81,10.41 19.81,9.53 20.19,9.53 20.32,9.4 22.61,9.4 22.61,6.86 23.37,6.1 23.37,0.64 50.17,0.64 50.17,7.62 50.8,8.26 54.61,8.26 54.61,52.07 50.8,52.07 50.17,52.71
  pour Top (no thermals): 0.76,6.98 7.24,6.98 7.24,0.64 0.76,0.64
  pour Top (no thermals): 0.76,64.64 7.87,64.64 7.87,58.42 0.76,58.42
  pour Bottom (no thermals): 37.72,48.9 37.72,49.28 38.1,49.28 38.1,52.83 37.85,52.83 37.85,53.21 39.88,53.21 39.88,52.83 39.5,52.83 39.62,49.28 39.88,49.28 39.88,48.9
  pour Route4 (no thermals): 0.89,64.64 8,64.64 8,58.17 0.89,58.17
  pour Route4 (no thermals): 0.76,7.24 7.87,7.24 7.87,0.76 0.76,0.76
  pour Route4 (no thermals): 42.67,7.24 49.78,7.24 49.78,0.76 42.67,0.76
  pour Route4 (no thermals): 42.8,64.64 49.91,64.64 49.91,58.17 42.8,58.17
  pour Route3 (no thermals): 42.93,64.64 50.04,64.64 50.04,58.17 42.93,58.17
  pour Route3 (no thermals): 0.89,64.64 8,64.64 8,58.17 0.89,58.17
  pour Route3 (no thermals): 0.76,7.24 7.87,7.24 7.87,0.76 0.76,0.76
  pour Route3 (no thermals): 42.93,7.24 50.04,7.24 50.04,0.76 42.93,0.76
  pour Route5 (no thermals): 42.93,7.24 50.04,7.24 50.04,0.76 42.93,0.76
  pour Route5 (no thermals): 0.76,64.77 7.87,64.77 7.87,58.29 0.76,58.29
  pour Route5 (no thermals): 0.89,7.24 8,7.24 8,0.76 0.89,0.76
  pour Route5 (no thermals): 42.93,64.64 50.04,64.64 50.04,58.17 42.93,58.17
ISOVCM
  Top 0.152: C12.1 10.54,35.05 10.54,36.13 R27.1
  Top 0.203: C12.1 10.79,35.05
  Top 1.016: 10.79,32.77 13.33,32.77
  pour Top (no thermals): 10.92,30.23 10.92,32.13 11.18,32.38 12.7,32.38 13.08,32.13 13.97,32.13 13.97,33.4 13.08,33.4 12.7,33.15 11.18,33.15 10.92,33.4 10.92,35.31 10.29,35.31 10.16,35.18 10.16,30.35 10.29,30.23
MODE
  Top 0.152: J2.3 28.07,54.74 | J2.3 J2.4 | J2.3 28.07,54.23 27.43,53.59 26.67,53.59 26.16,53.09 26.16,39.62 26.42,39.37 26.42,36.32 26.16,36.07 26.16,34.19 | 26.16,33.27 26.17,33.26 U2.58
  Top 0.254: 26.16,33.27 26.16,34.19
N$1
  Bottom 0.203: C2.2 20.83,6.86 20.95,6.98 T2.4
N$2
  Bottom 0.203: C1.2 23.5,6.86 T2.5
N$3
  Bottom 0.889: 22.22,10.29 22.22,13.33
  pour Bottom (no thermals): 25.78,10.39 24.28,10.39 24,10.67 22.86,10.67 22.61,10.92 22.61,12.83 22.86,13.08 22.86,13.84 21.59,13.84 21.59,13.08 21.84,12.83 21.84,10.92 21.59,10.67 20.45,10.67 20.19,10.41 18.67,10.41 18.67,9.53 20.19,9.53 20.32,9.4 24.13,9.4 24.26,9.53 25.78,9.53
N$4
  Bottom 0.203: C2.1 21.71,6.72 21.72,6.1
  Bottom 0.406: J7.1 21.72,5.21 21.72,6.1
N$5
  Top 0.813: 5.71,33.27 5.97,33.27
N$6
  Bottom 0.152: R5.1 22.67,15.55 22.48,15.37 22.48,14.73 22.61,14.61 C4.2 22.7,14.51 23.62,13.59 23.56,13.53 R2.1 23.56,11.88 T2.1
N$7
  Bottom 0.152: R4.1 21.78,15.55 21.97,15.37 21.97,14.86 21.72,14.61 C4.1 21.75,14.51 20.83,13.59 20.89,13.53 R1.1 20.89,11.88 T2.3
N$8  (via drill 0.25 pad 0.51)
  Top 0.152: 22.6,23.37 22.61,23.37 | 22.6,23.37 R41.2 | v22,23.04 22.28,23.04 22.6,23.37
  Top 0.203: R41.2 23.16,24.03 U2.17
  Top 0.254: U2.17
  Bottom 0.152: R4.2 21.71,16.45 22.07,16.82 22.07,22.96 v22,23.04
N$9  (via drill 0.25 pad 0.51)
  Top 0.152: 22.63,22.76 22.61,22.63 | 22.63,22.76 R41.1 | v22.61,22.48 22.61,22.61 22.63,22.76
  Top 0.203: R41.1 23.67,23.85 U2.18
  Top 0.254: U2.18
  Bottom 0.152: R5.2 22.74,16.45 22.38,16.82 22.38,22.25 v22.61,22.48
N$10
  Bottom 0.203: R6.2 24.26,56.52 24.62,56.88 J2.2 26.07,57.82 27.43,59.18 R7.2 27.3,59.18 27.3,59.44
N$11
  Bottom 0.203: R8.1 31.88,56.52 31.51,56.88 J2.6 30.07,57.82 28.7,59.18 R7.1 28.83,59.44
N$12
  Top 0.152: 32.89,4.83 J3.4 32.77,4.83 31.88,5.71 30.1,5.71 29.84,5.97 29.84,14.73 24.64,19.94 24.64,22.61 24.77,22.73 24.77,23.7 24.66,23.8
  Top 0.203: U2.20 24.69,24.41 24.66,24.38 24.66,23.8
N$13
  Top 0.406: C7.1 7.28,31.28 7.49,31.5 T1.4
N$14  (via drill 0.41)
  Top 0.152: U2.6 22.5,30.1 21.61,30.1 C13.2
  Top 0.406: C17.1 19.94,29.46 v19.05,29.46
  Bottom 0.406: v19.05,29.46 C15.1
  pour Top (no thermals): 22.86,30.71 22.86,29.95 20.95,29.95 20.62,29.64 20.62,29.21 19.66,29.21 19.66,30.23 20.09,30.71
N$15
  Top 0.152: U2.8 21.68,29.08 C13.1
  pour Top (no thermals): 22.86,28.96 21.06,28.96 21.06,29.69 22.86,29.69
N$16
  Top 0.127: U4.6 R39.1
  Top 0.152: U2.30 29.67,23.92 30.53,23.06 34.19,23.06 34.57,23.44 40.44,23.44 40.59,23.6 40.62,23.57 R39.1
N$17
  Top 0.406: R9.1 14.85,34.11 13.59,34.11 R11.2 12.05,34.1 11.96,34.01 T1.1
N$18
  Top 0.152: 22.54,28.07 22.61,28.07 | 22.54,28.07 U2.10 | C14.2 21.63,28.07 22.54,28.07
  pour Top (no thermals): 22.86,27.94 21.06,27.94 21.06,28.7 22.86,28.7
N$19
  Top 0.406: R10.1 R12.2 12,31.43 T1.3
N$20
  Top 0.406: R23.2 17.97,33.21 17.83,33.07 15.21,33.07 15.08,33.21 R9.2
  pour Top (no thermals): 20.68,33.38 20.68,33.05 20.19,33.05 19.86,32.94 19.28,32.94 18.9,33.05 18.19,33.05 18.19,33.25 18.9,33.25 19.28,33.4 19.84,33.4 20.19,33.38
N$21
  Top 0.127: U3.45 50.31,39.94 50.39,39.85 50.57,39.85 51,40.28 51,41.71 51.54,42.24 51.54,46.97 53.34,48.77 55.09,48.77 55.35,49.02 55.37,49 J1.8
N$22
  Top 0.406: R23.1 17.97,32.32 17.83,32.46 15.21,32.46 15.09,32.33 14.92,32.32 R10.2
  pour Top (no thermals): 20.7,32.49 20.32,32.49 19.84,32.59 19.28,32.59 18.9,32.49 18.31,32.49 18.31,32.26 18.9,32.26 19.28,32.13 19.99,32.13 20.32,32.16 20.7,32.16
N$23
  Top 0.127: U4.45 50.31,24.57 50.39,24.49 51.08,24.49 52.93,26.34 55.12,26.34 55.35,26.57 J1.56
N$24
  Top 0.152: R27.2 11.5,37.02 11.94,37.47 R15.2
N$25  (via drill 0.41)
  Top 0.152: U2.12 22.5,27.05 21.7,27.05 C14.1
  Top 0.406: C17.2 20.14,28.14 20.19,28.19 v19.05,28.19
  Bottom 0.406: v19.05,28.19 C16.2
  pour Top (no thermals): 22.86,27.71 20.93,27.71 20.62,28.02 20.62,28.42 19.66,28.42 19.66,27.38 20.09,26.95 22.86,26.95
N$27
  Top 0.127: U4.44 50.28,24.07 50.37,24.16 51.21,24.16 53.06,26.01 55.12,26.01 55.37,25.76 | 55.37,25.76 | 55.37,25.76 J1.58
N$28
  Top 0.127: U4.43 50.32,23.57 50.39,23.5 52.43,23.5 52.88,23.95 55.12,23.95 55.35,24.18 J1.62
N$29
  Top 0.127: U4.35 50.3,19.57 50.39,19.48 50.72,19.48 53.47,16.74 55.07,16.74 55.32,16.99 55.34,16.98 J1.80
N$30
  Top 0.127: U4.34 50.29,19.07 50.37,19.15 50.62,19.15 53.37,16.41 55.09,16.41 55.35,16.15 J1.82
N$31
  Top 0.127: U3.44 50.28,39.44 50.37,39.52 50.65,39.52 51.26,40.13 51.26,41.55 51.82,42.11 51.82,46.84 53.39,48.41 55.12,48.41 55.37,48.16 | 55.37,48.16 | 55.37,48.16 J1.10
N$32
  Top 0.152: U2.55 27.67,34.07 27.56,34.19 27.56,35.18 33.27,40.89 38.25,40.89 38.38,40.77 R3.2
N$33
  Top 0.127: 42.11,39.93 | 42.11,39.93 U3.4 | R17.1 42.11,39.93
  Top 0.152: U2.54 28.17,34.04 28.25,34.11 28.25,35.15 32.92,39.83 40.36,39.83 40.51,39.98 40.56,39.93 R17.1
N$34
  Top 0.127: U3.43 50.29,38.94 50.37,38.86 50.57,38.86 51.61,39.9 51.61,41.35 52.2,41.94 52.2,45.01 53.59,46.38 55.19,46.38 55.37,46.58 | 55.37,46.58 | 55.37,46.58 J1.14
N$35
  Top 0.127: U3.5 42.11,39.45 | U3.5 | R17.2 40.67,39.45 U3.5
  Top 0.152: U2.53 28.67,33.99 28.55,34.11 28.55,35 33.07,39.52 40.36,39.52 40.46,39.42 R17.2
N$36
  Top 0.127: U3.42 50.3,38.44 50.39,38.53 50.62,38.53 51.87,39.78 51.87,41.22 52.45,41.81 52.45,44.88 53.57,46 55.14,46 J1.16 | J1.16 | J1.16
N$37
  Top 0.152: U2.56 27.17,34.11 27.25,34.19 27.25,35.33 33.12,41.2 38.33,41.2 38.41,41.28 R3.1
N$38
  Bottom 0.152: 31.88,6.86 R24.1 | J3.1 30.86,6.86 31.88,6.86 | J3.2 32.89,6.86 31.88,6.86
N$39
  Top 0.127: U4.14 42.09,19.56 40.67,19.56 R43.1
  Top 0.152: U2.22 25.67,24 25.58,23.9 25.58,22.22 28.32,19.48 40.44,19.48 40.59,19.63 R43.1
N$41
  Bottom 0.203: R25.1 36.18,49.92 36.2,49.91 36.59,50.3 U5.8
  Bottom 0.254: R25.1 34.05,49.92 SJ1.2
N$44
  Top 0.127: U4.10 42.11,21.57 | U4.10 | R42.1 U4.10
  Top 0.152: U2.24 26.67,23.78 26.57,23.67 26.57,22.61 28.7,20.47 34.8,20.47 35.79,21.46 40.44,21.46 40.54,21.57 R42.1
N$60
  Top 0.127: U3.41 50.28,37.94 50.37,37.85 50.55,37.85 50.85,38.12 50.85,38.3 52.22,39.68 52.22,41.1 52.78,41.66 52.78,43.41 53.34,43.97 55.14,43.97 55.37,44.19 | 55.37,44.19 55.37,44.2 | 55.37,44.19 J1.20
N$62
  Bottom 0.203: J1.97 52.07,9.78 R29.1
N$63
  Top 0.127: U3.40 50.32,37.44 50.39,37.52 50.62,37.52 51.13,38.02 51.13,38.2 52.5,39.57 52.5,40.97 53.06,41.53 53.06,43.31 53.34,43.59 55.14,43.59 55.37,43.36 | 55.37,43.36 | 55.37,43.36 J1.22
N$66
  Top 0.127: U3.6 R18.1
  Top 0.152: U2.52 29.17,33.98 29.31,34.11 29.31,35.03 33.12,38.84 40.36,38.84 40.46,38.94 R18.1
N$67
  Top 0.127: U3.7 42.11,38.43 | U3.7 | R18.2 U3.7
  Top 0.152: U2.51 29.67,34.05 29.62,34.11 29.62,34.87 33.27,38.53 40.36,38.53 40.46,38.43 R18.2
N$68
  Top 0.127: U3.8 42.09,37.95 R19.1
  Top 0.152: U2.48 32.06,32.58 32.13,32.51 32.36,32.51 37.69,37.85 40.44,37.85 40.54,37.95 R19.1
N$69
  Top 0.127: U3.9 42.11,37.44 | U3.9 | R19.2 U3.9
  Top 0.152: U2.47 32,32.08 32.13,32.21 32.51,32.21 37.85,37.54 40.36,37.54 40.46,37.44 R19.2
N$70
  Top 0.127: U3.10 R20.1
  Top 0.152: U2.46 32.04,31.58 32.28,31.83 33.27,31.83 38.3,36.86 40.44,36.86 40.51,36.93 R20.1
N$71
  Top 0.127: U3.11 42.09,36.45 40.67,36.45 R20.2
  Top 0.152: R20.2 40.49,36.42 40.36,36.55 38.46,36.55 33.43,31.52 32.44,31.52 31.99,31.08 U2.45
N$72
  Top 0.127: U3.39 50.29,36.94 50.37,36.86 50.57,36.86 51.41,37.69 51.41,38.05 52.81,39.45 52.81,40.64 53.72,41.55 55.14,41.55 55.37,41.78 | 55.37,41.78 | 55.37,41.78 J1.26
N$73
  Top 0.127: U3.38 50.26,36.44 50.34,36.53 50.65,36.53 51.69,37.57 51.69,37.92 53.09,39.32 53.09,40.51 53.77,41.2 55.12,41.2 55.37,40.95 | 55.37,40.95 | 55.37,40.95 J1.28
N$74
  Top 0.127: U3.35 50.3,34.94 50.39,34.85 51.05,34.85 51.44,35.23 51.44,36.65 52.76,38 52.76,38.48 53.47,39.19 55.17,39.19 55.35,39.38 J1.32
N$75
  Top 0.127: U3.34 50.31,34.44 50.39,34.52 51.16,34.52 51.74,35.1 51.71,36.45 53.04,37.77 53.06,38.35 53.49,38.79 55.12,38.79 55.35,38.56 J1.34
N$76
  Top 0.127: U3.33 50.32,33.94 50.39,33.86 51.05,33.86 52.25,35.05 52.25,36.02 52.98,36.75 55.14,36.75 J1.38 | J1.38 55.37,36.98 | J1.38
N$77
  Top 0.127: U3.32 50.28,33.44 50.37,33.53 51.18,33.53 52.55,34.9 52.55,35.89 53.06,36.4 55.12,36.4 55.35,36.17 55.35,36.18 J1.40
N$78
  Top 0.127: U3.31 50.32,32.94 50.39,32.87 51.28,32.87 52.76,34.34 55.12,34.34 55.37,34.59 | 55.37,34.59 55.37,34.6 | 55.37,34.59 J1.44
N$79
  Top 0.127: U3.30 50.29,32.44 50.37,32.51 51.38,32.51 52.86,33.99 55.17,33.99 J1.46
N$80
  Top 0.127: U3.29 50.33,31.94 50.42,31.85 53.75,31.85 54.08,32.18 J1.50
N$81
  Top 0.127: U3.28 50.31,31.44 50.39,31.52 55.17,31.52 55.35,31.34 55.37,31.37 J1.52
N$83
  Top 0.127: U3.21 40.67,31.45
  Top 0.152: U2.35 31.95,26.08 32.05,26.19 35.03,26.19 40.28,31.45 40.67,31.45 R30.2
N$84
  Top 0.127: U3.20 42.09,31.93 R30.1
  Top 0.152: U2.36 31.97,26.58 32.05,26.49 34.87,26.49 40.21,31.83 40.44,31.83 40.51,31.9 40.62,31.93 R30.1
N$85
  Top 0.127: U3.14 42.09,34.95 R21.1
  Top 0.152: U2.44 32.1,30.58 32.59,31.06 34.11,31.06 37.92,34.87 40.36,34.87 40.44,34.95 R21.1
N$86
  Top 0.127: U3.15 R21.2
  Top 0.152: R21.2 40.49,34.44 40.36,34.57 38.08,34.57 34.27,30.76 32.74,30.76 32.05,30.07 31.37,30.07 31.36,30.08 U2.43
N$87
  Top 0.127: U3.16 R22.1
  Top 0.152: U2.40 31.95,28.58 32.05,28.47 34.34,28.47 39.68,33.81 40.44,33.81 40.59,33.96 40.62,33.93 R22.1
N$88
  Top 0.127: U3.17 42.09,33.45 40.67,33.45 R22.2
  Top 0.152: U2.39 31.96,28.08 32.05,28.17 34.49,28.17 39.83,33.5 40.51,33.5 40.59,33.43 R22.2
N$89
  Top 0.127: U3.18 42.11,32.94 | U3.18 | R28.1 U3.18
  Top 0.152: U2.38 31.96,27.58 32.05,27.48 34.72,27.48 40.06,32.82 40.44,32.82 40.59,32.97 40.62,32.94 R28.1
N$90
  Top 0.127: U3.19 R28.2
  Top 0.152: U2.37 31.96,27.08 32.05,27.18 34.87,27.18 40.21,32.51 40.51,32.51 40.59,32.44 R28.2
N$91
  Top 0.127: U4.42 50.3,23.07 50.37,23.14 52.6,23.14 53.06,23.6 55.14,23.6 J1.64 | J1.64 55.37,23.37 | J1.64
N$92
  Top 0.127: U4.41 50.3,22.57 50.39,22.48 52.17,22.48 53.09,21.57 55.17,21.57 J1.68
N$93
  Top 0.127: U4.40 50.29,22.07 50.37,22.15 52.07,22.15 53.01,21.18 55.12,21.18 55.35,20.97 J1.70
N$94
  Top 0.127: U4.39 50.31,21.57 50.39,21.49 51.77,21.49 52.58,20.68 52.58,19.71 53.14,19.15 55.14,19.15 J1.74 | J1.74 | J1.74
N$95
  Top 0.127: U4.38 50.28,21.07 50.37,21.16 51.61,21.16 52.25,20.52 52.25,19.58 53.04,18.8 55.12,18.8 55.35,18.57 J1.76
N$98
  Top 0.127: 40.67,24.59 R38.1 40.67,24.56 U4.4 | U4.4 42.11,24.56 | U4.4
  Top 0.152: U2.32 30.67,24.14 30.99,23.82 33.5,23.82 34.11,24.43 40.44,24.43 40.59,24.59 R38.1
N$99
  Top 0.127: 40.67,24.08 R38.2 42.09,24.08 U4.5
  Top 0.152: U2.31 30.17,24.11 30.76,23.52 33.66,23.52 34.27,24.13 40.44,24.13 40.51,24.05 40.54,24.08 R38.2
N$100
  Top 0.127: U4.7 R39.2
  Top 0.152: U2.29 29.17,23.96 30.38,22.76 34.34,22.76 34.72,23.14 40.44,23.14 40.51,23.06 R39.2
N$102
  Top 0.127: U4.8 42.09,22.58 R40.1
  Top 0.152: U2.28 28.67,23.93 30.45,22.15 34.87,22.15 35.18,22.45 40.44,22.45 40.59,22.61 40.62,22.58 R40.1
N$103
  Top 0.127: U4.9 42.11,22.07 | U4.9 | R40.2 U4.9
  Top 0.152: U2.27 28.17,23.97 30.3,21.84 35.1,21.84 35.41,22.15 40.36,22.15 40.44,22.07 R40.2
N$104
  Top 0.127: 42.11,21.08 | 42.11,21.08 U4.11 | R42.2 40.67,21.08 42.11,21.08
  Top 0.152: U2.23 26.17,23.76 26.26,23.67 26.26,22.45 28.55,20.17 34.95,20.17 35.94,21.16 40.36,21.16 40.46,21.06 R42.2
N$106
  Top 0.127: U4.15 R43.2
  Top 0.152: U2.21 25.17,24 25.27,23.9 25.27,22.07 28.17,19.18 40.36,19.18 40.46,19.07 R43.2
N$119
  Top 0.61: C6.1 3.17,33.31 J5.1
N$126
  Bottom 0.203: U5.6 40.49,49.8 40.89,49.4 41.4,49.4 41.53,49.28 C38.2
N$137
  Top 0.406: T1.5 7.87,34.04 7.75,34.16 7.11,34.16 6.98,34.29 C6.2
OE  (via drill 0.3)
  Top 0.203: U3.13 40.89,35.44 v40.64,35.69 | U4.13 40.89,20.07 v40.64,20.32
  Route5 0.203: v40.64,35.69 40.01,35.05 40.01,20.95 v40.64,20.32 40.01,19.68 40.01,13.08 40.51,12.57 v46.74,12.57
  Bottom 0.203: R16.2 48.64,8.89 | v46.74,12.57 46.74,11.3 47.24,10.79 47.24,9.27 47.68,8.84 R16.2 | R16.2 48.51,8.76 48.62,8.82 49.2,8.81 49.49,8.97 J1.99
OVDD  (via drill 0.3)
  Top 0.152: C20.1 28.56,23.11 29.79,21.87 v29.79,21.34
  Top 0.203: C21.1 32.51,25.53 32.46,25.58
  Top 0.254: U2.34 32.46,25.58 32.64,25.4 | U2.49 30.67,33.4 v31.5,33.4 | U2.42 32.5,29.58 32.51,29.59 C22.1 32.51,29.64 32.69,29.82 32.69,29.87 33.07,30.25 v35.13,30.25 | U2.26 27.67,23.91 27.71,23.88 27.71,23.14 27.69,23.11 C20.1
  Top 0.305: 32.64,25.4 v33.53,25.4
  Bottom 0.406: R37.2 v31.5,33.4
  pour Top (no thermals): 32.79,25.78 31.85,25.78 31.75,25.68 31.01,25.68 31.01,25.48 31.75,25.48 32.05,25.17 32.79,25.17
  pour Top (no thermals): 31.47,34.65 31.47,33.86 31.22,33.6 31.19,33.58 30.58,33.58 30.58,32.92 31.47,32.92 32.05,33.5 32.05,34.65
  pour Route5: 30.99,33.91 35.43,33.91 35.43,24.26 32,20.83 29.59,20.83 29.59,23.37 30.99,24.77
SCL  (via drill 0.3)
  Top 0.203: U1.6 50.35,10.22 50.55,10.41 50.55,12.32 v51.18,12.95
  Bottom 0.203: 55.37,13.72 | J1.87 55.37,13.72 | 55.37,13.72 55.25,13.84 | 55.37,13.84 J1.87 | J1.87 55.3,13.78 55.25,13.72 51.94,13.72 v51.18,12.95 R46.2 50.29,12.95
SDA  (via drill 0.3)
  Top 0.203: v51.18,11.56 51.18,10.03 50.67,9.53 49.4,9.53 49.28,9.66 U1.5
  Bottom 0.203: J1.91 55.26,12.17 55.25,12.19 51.82,12.19 v51.18,11.56 50.29,11.56 50.36,11.62 R26.1
SENSE
  Top 0.203: J4.2 21.57,54.88 21.59,54.86 21.59,53.85 21.84,53.59 25.15,53.59 25.65,53.09 25.65,39.5 25.15,38.99 25.15,37.47 25.75,36.87 C19.1
  Top 0.254: C19.1 25.78,36.83 25.67,36.72 U2.59
  Bottom 0.203: J4.4 19.56,54.86 19.54,54.88 | J4.2 21.48,54.88 21.46,54.86 21.45,54.88
  Bottom 0.406: 19.54,54.88 J4.6 | 21.45,54.88 J4.4
SHDN
  Top 0.152: J3.3 30.1,4.83 29.46,5.46 29.46,14.61 24.28,19.79 24.28,22.71 24.38,22.81 24.38,23.52 24.18,23.72
  Top 0.203: U2.19 24.18,24.43 24.18,23.72
VCM
  Top 0.152: J4.3 19.56,56.9 | C18.1 24.64,36.45 23.62,37.47 R15.1
  Top 0.203: 19.56,56.9 19.56,59.18 20.19,59.82 22.35,59.82 22.86,60.33 TP6.1 | J4.3 19.56,56.64 20.57,55.63 20.57,53.59 20.95,53.21 24.77,53.21 25.15,52.83 25.15,39.75 24.64,39.24 24.64,36.45 24.64,36.32 24.64,36.4 C18.1
  Top 0.254: C18.1 24.51,36.45 24.64,36.32 25.17,35.79 U2.60
VROM  (via drill 0.3)
  Top 0.305: U1.8 47.71,11.52 v47.5,11.56
  Bottom 0.203: 49.48,11.63 49.46,11.65 R26.2 | R46.1 49.53,12.95 49.46,12.89 R26.2 | R26.2 49.53,11.68 49.44,11.59 C27.1 | 48.39,10.92 48.39,11.56
  Bottom 0.305: J1.93 52.14,11.38 51.56,10.79 48.51,10.79 48.39,10.92 | C27.1 48.39,11.56 v47.5,11.56

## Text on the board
Top: 4
Route2: LAYER 2, PWR/GND PLANE, POS IMAGE | 5
Route3: LAYER 3, PWR/GND PLANES, POS IMAGE | 6
Route4: LAYER 4, PWR/GND PLANES, POS IMAGE | 7
Route5: LAYER 5, PWR/GND PLANES, POS IMAGE | 8
Bottom: 9
tPlace: REF | GND | VCM | GND | +2.5V | +3.3V | EXT | OPTION | 2/3 | 1/3 | AUX | MODE | SENSE | EXT | VCM | 2.5V | VDD | GND | DC997B- | LTC2242 FAMILY LVDS BUS | LTC22 CUP | BIT | Msps | AIN | SHDN | 0E# | (408)432-1900 | www.linear.com | LTC CONFIDENTIAL | FOR CUSTOMER | USE ONLY | VDD | GND | ENCODE | CLK | 2
bPlace: 11
tStop: 3
bStop: 10
tCream: 1
bCream: 12
bRestrict: ETLJQT
Measures: 1.900 | 0.125 | 2.475 | 2.175 | 2.575 | 1.125 | 0.100 | -0.050 | 0 | 1.575 | 0.300 | 0 | FIDUCIALS 3X | GRID ORIGIN | TOOLING HOLES 2X 0.070 UPLTD | 2.255 | -0.050
Document: LTC2242 FAMILY LVDS BUS | DC997 | B2 | E.TRELEWICZ | 12 | 08/29/06
Reference: B1 | INITIAL RELEASE | 08/14/06 | TRELEWICZ | B2 | INCORP SILKSCRN & DOC UPDATES | 08/29/06 | TRELEWICZ | 1 | 0.0063" | 1 | 0.0140" | 1 | 0.0011" | 1 | 0.0140" | 1 | 0.0063" | 1 | FIGURE A | DC997 REV: B2 | DRILL LEGEND | SYM SIZE QTY TOLERANCE PLTD | 57 | +0/-.010 | YES | .010 | .012 | 417 | +0/-.012 | YES | .016 | 3 | +/- .003 | YES | .020 | 0 | +/- .003 | YES | .032 | 21 | +/- .003 | YES | TRELWICZ | .066 | 6 | +/- .003 | YES | LTC2242 FAMILY LVDS BUS | .070 | 2 | +.004/-0 | NO | .188 | 4 | +/- .003 | YES | TRELWICZ | TRELWICZ | DC997 | A | B2 | 1 | 1
tDocu: TP6 | TP3 | TP4 | TP5 | TP1 | TP2 | GND | VCM | GND | +2.5V | +3.3V | EXTREF | OPTION | 2/3 | 1/3 | AUX | MODE | SENSE | EXT | VCM | 2.5V | VDD | GND | DC997B | LTC2242 FAMILY LVDS BUS | (408)432-1900 | www.linear.com | LTC CONFIDENTIAL | FOR CUSTOMER | USE ONLY | LTC2242 FAMILY LVDS BUS | DC997 | B2 | E.TRELEWICZ | 08/29/06
bDocu: LTC2242 FAMILY LVDS BUS | DC997 | B2 | ETRELEWICZ | 08/29/06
